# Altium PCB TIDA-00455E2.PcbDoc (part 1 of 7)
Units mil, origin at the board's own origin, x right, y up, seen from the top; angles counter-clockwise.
Board outline 6693 x 6693.1 mil, 8 copper layers (Layer 1 - Top Layer, Layer 2 - GND, Layer 3 - Sensitive, Layer 4 - GND, Layer 5 - PWR, Layer 6 - Signal, Layer 7 - GND, Layer 8 - Bottom Layer), stack 63.122 mil thick; 537 components, 407 nets, 1686 pads, 1249 vias.
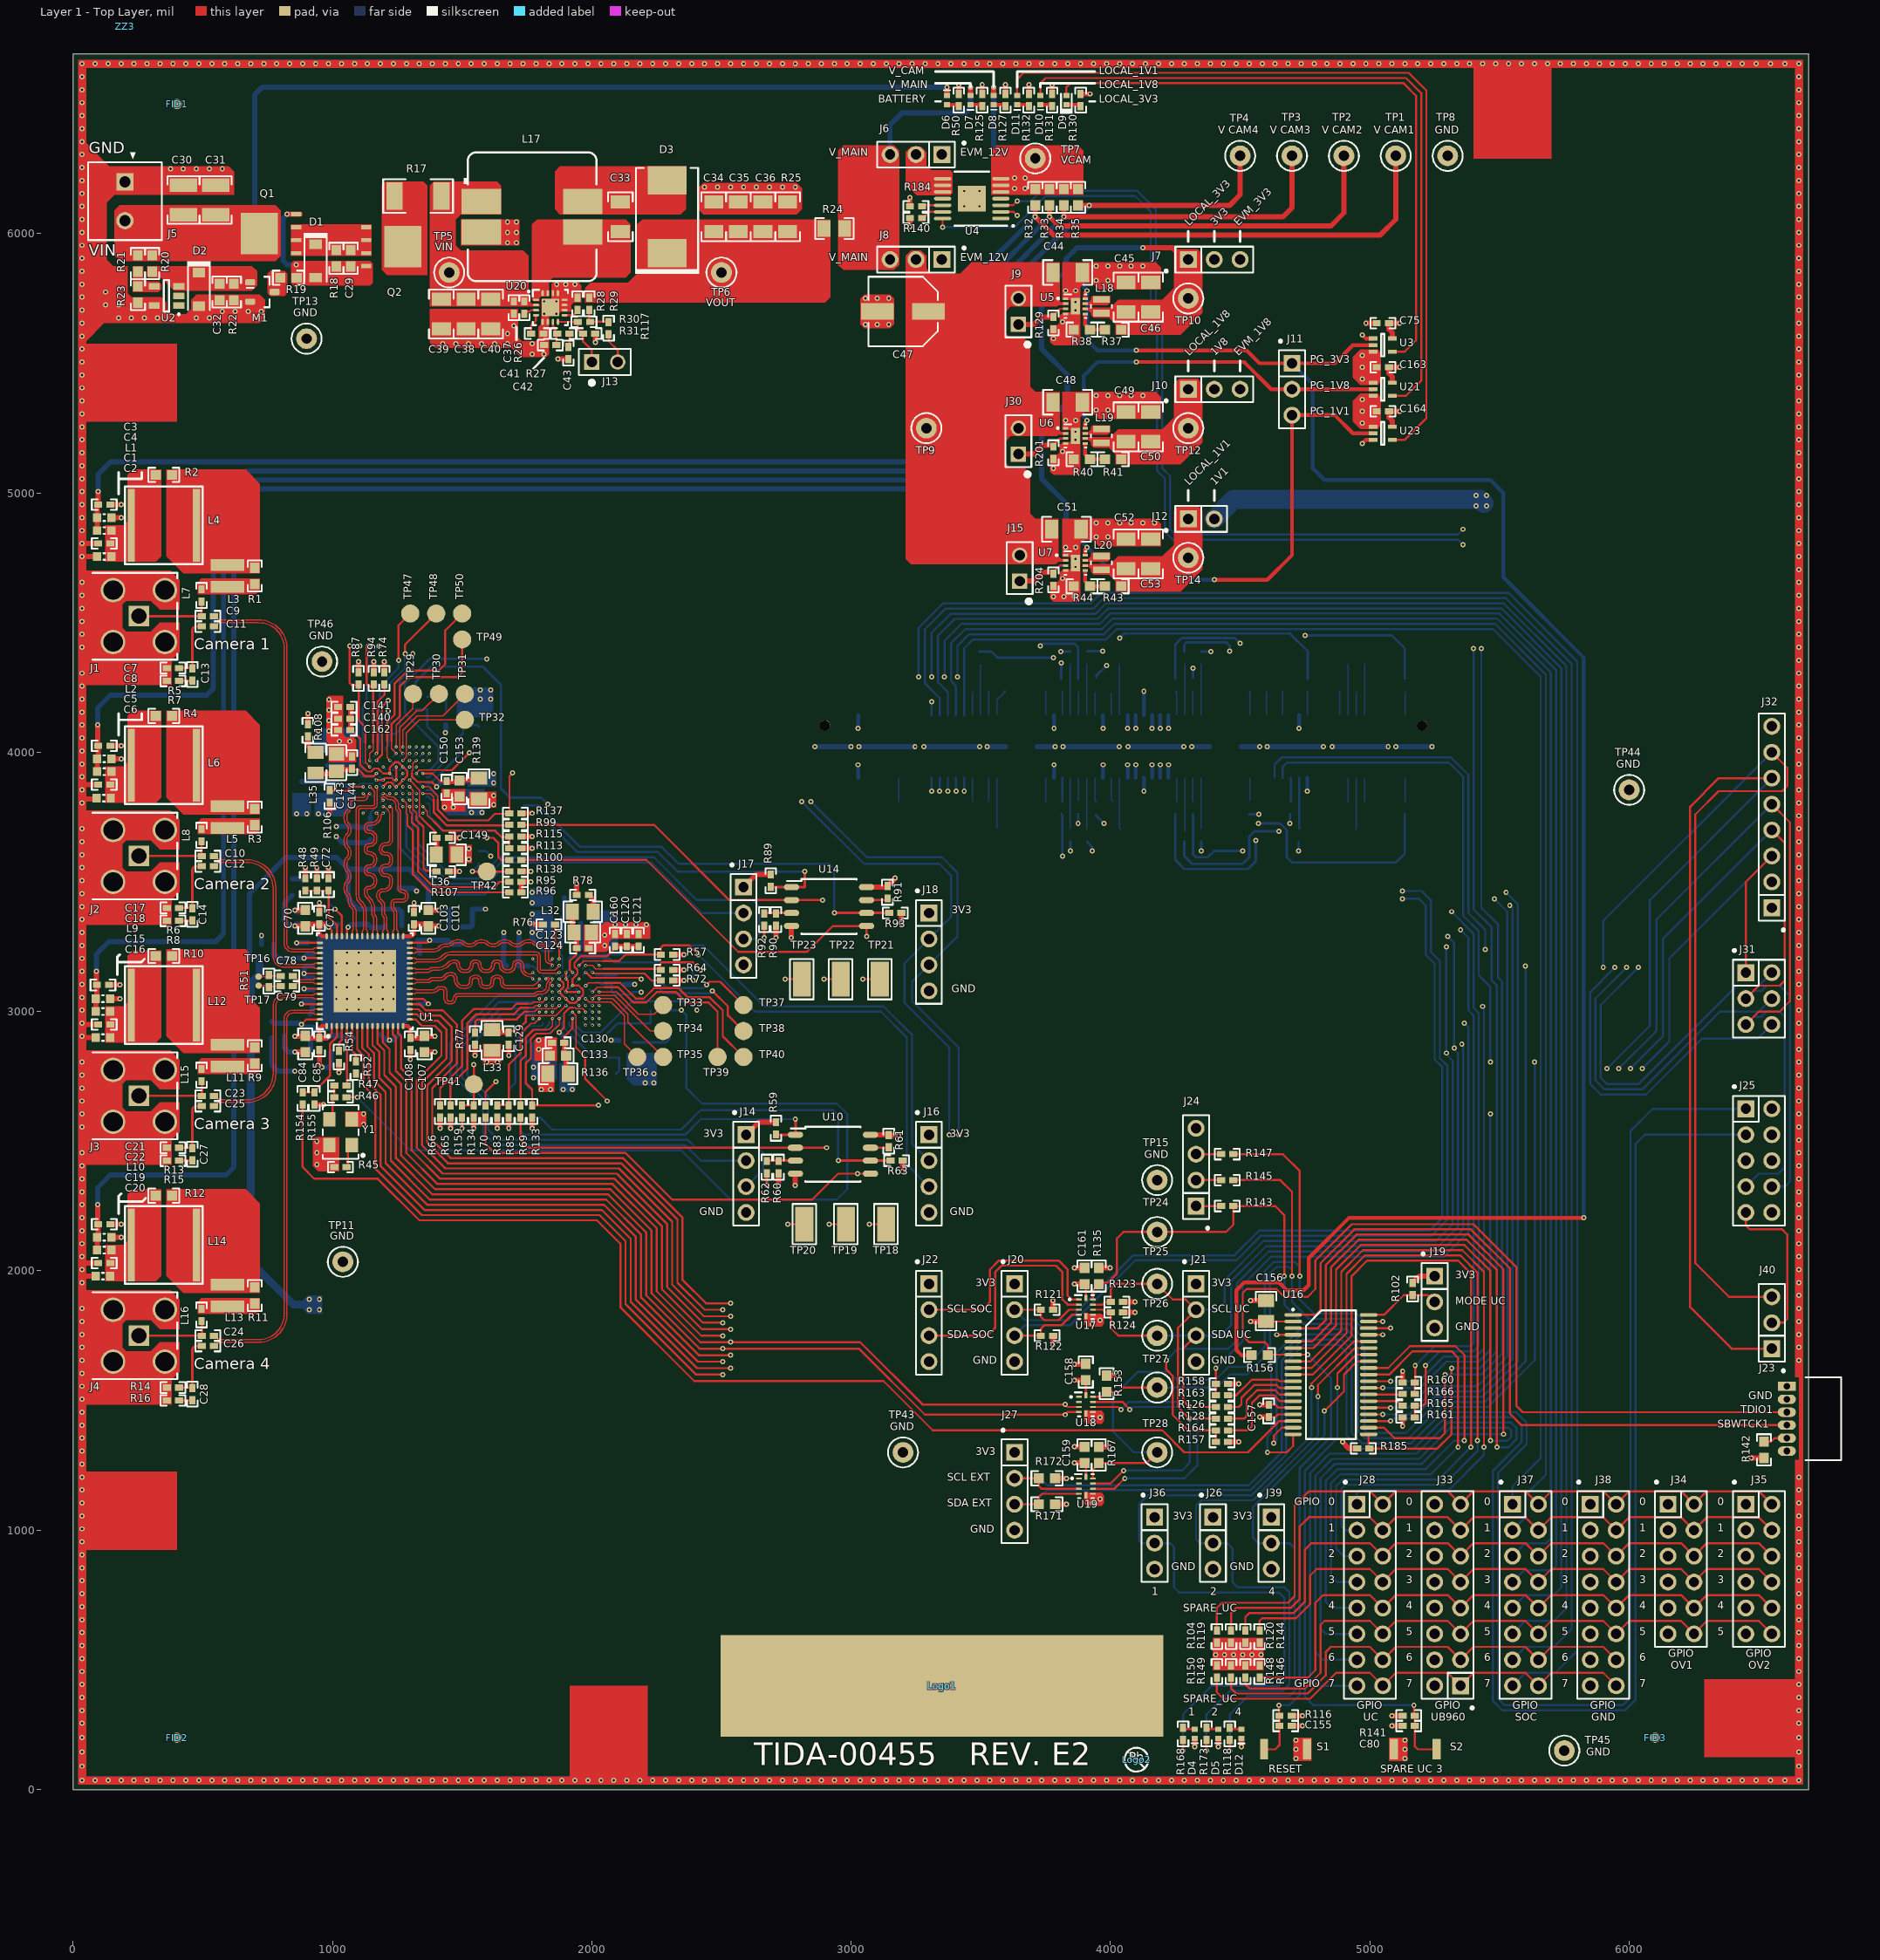
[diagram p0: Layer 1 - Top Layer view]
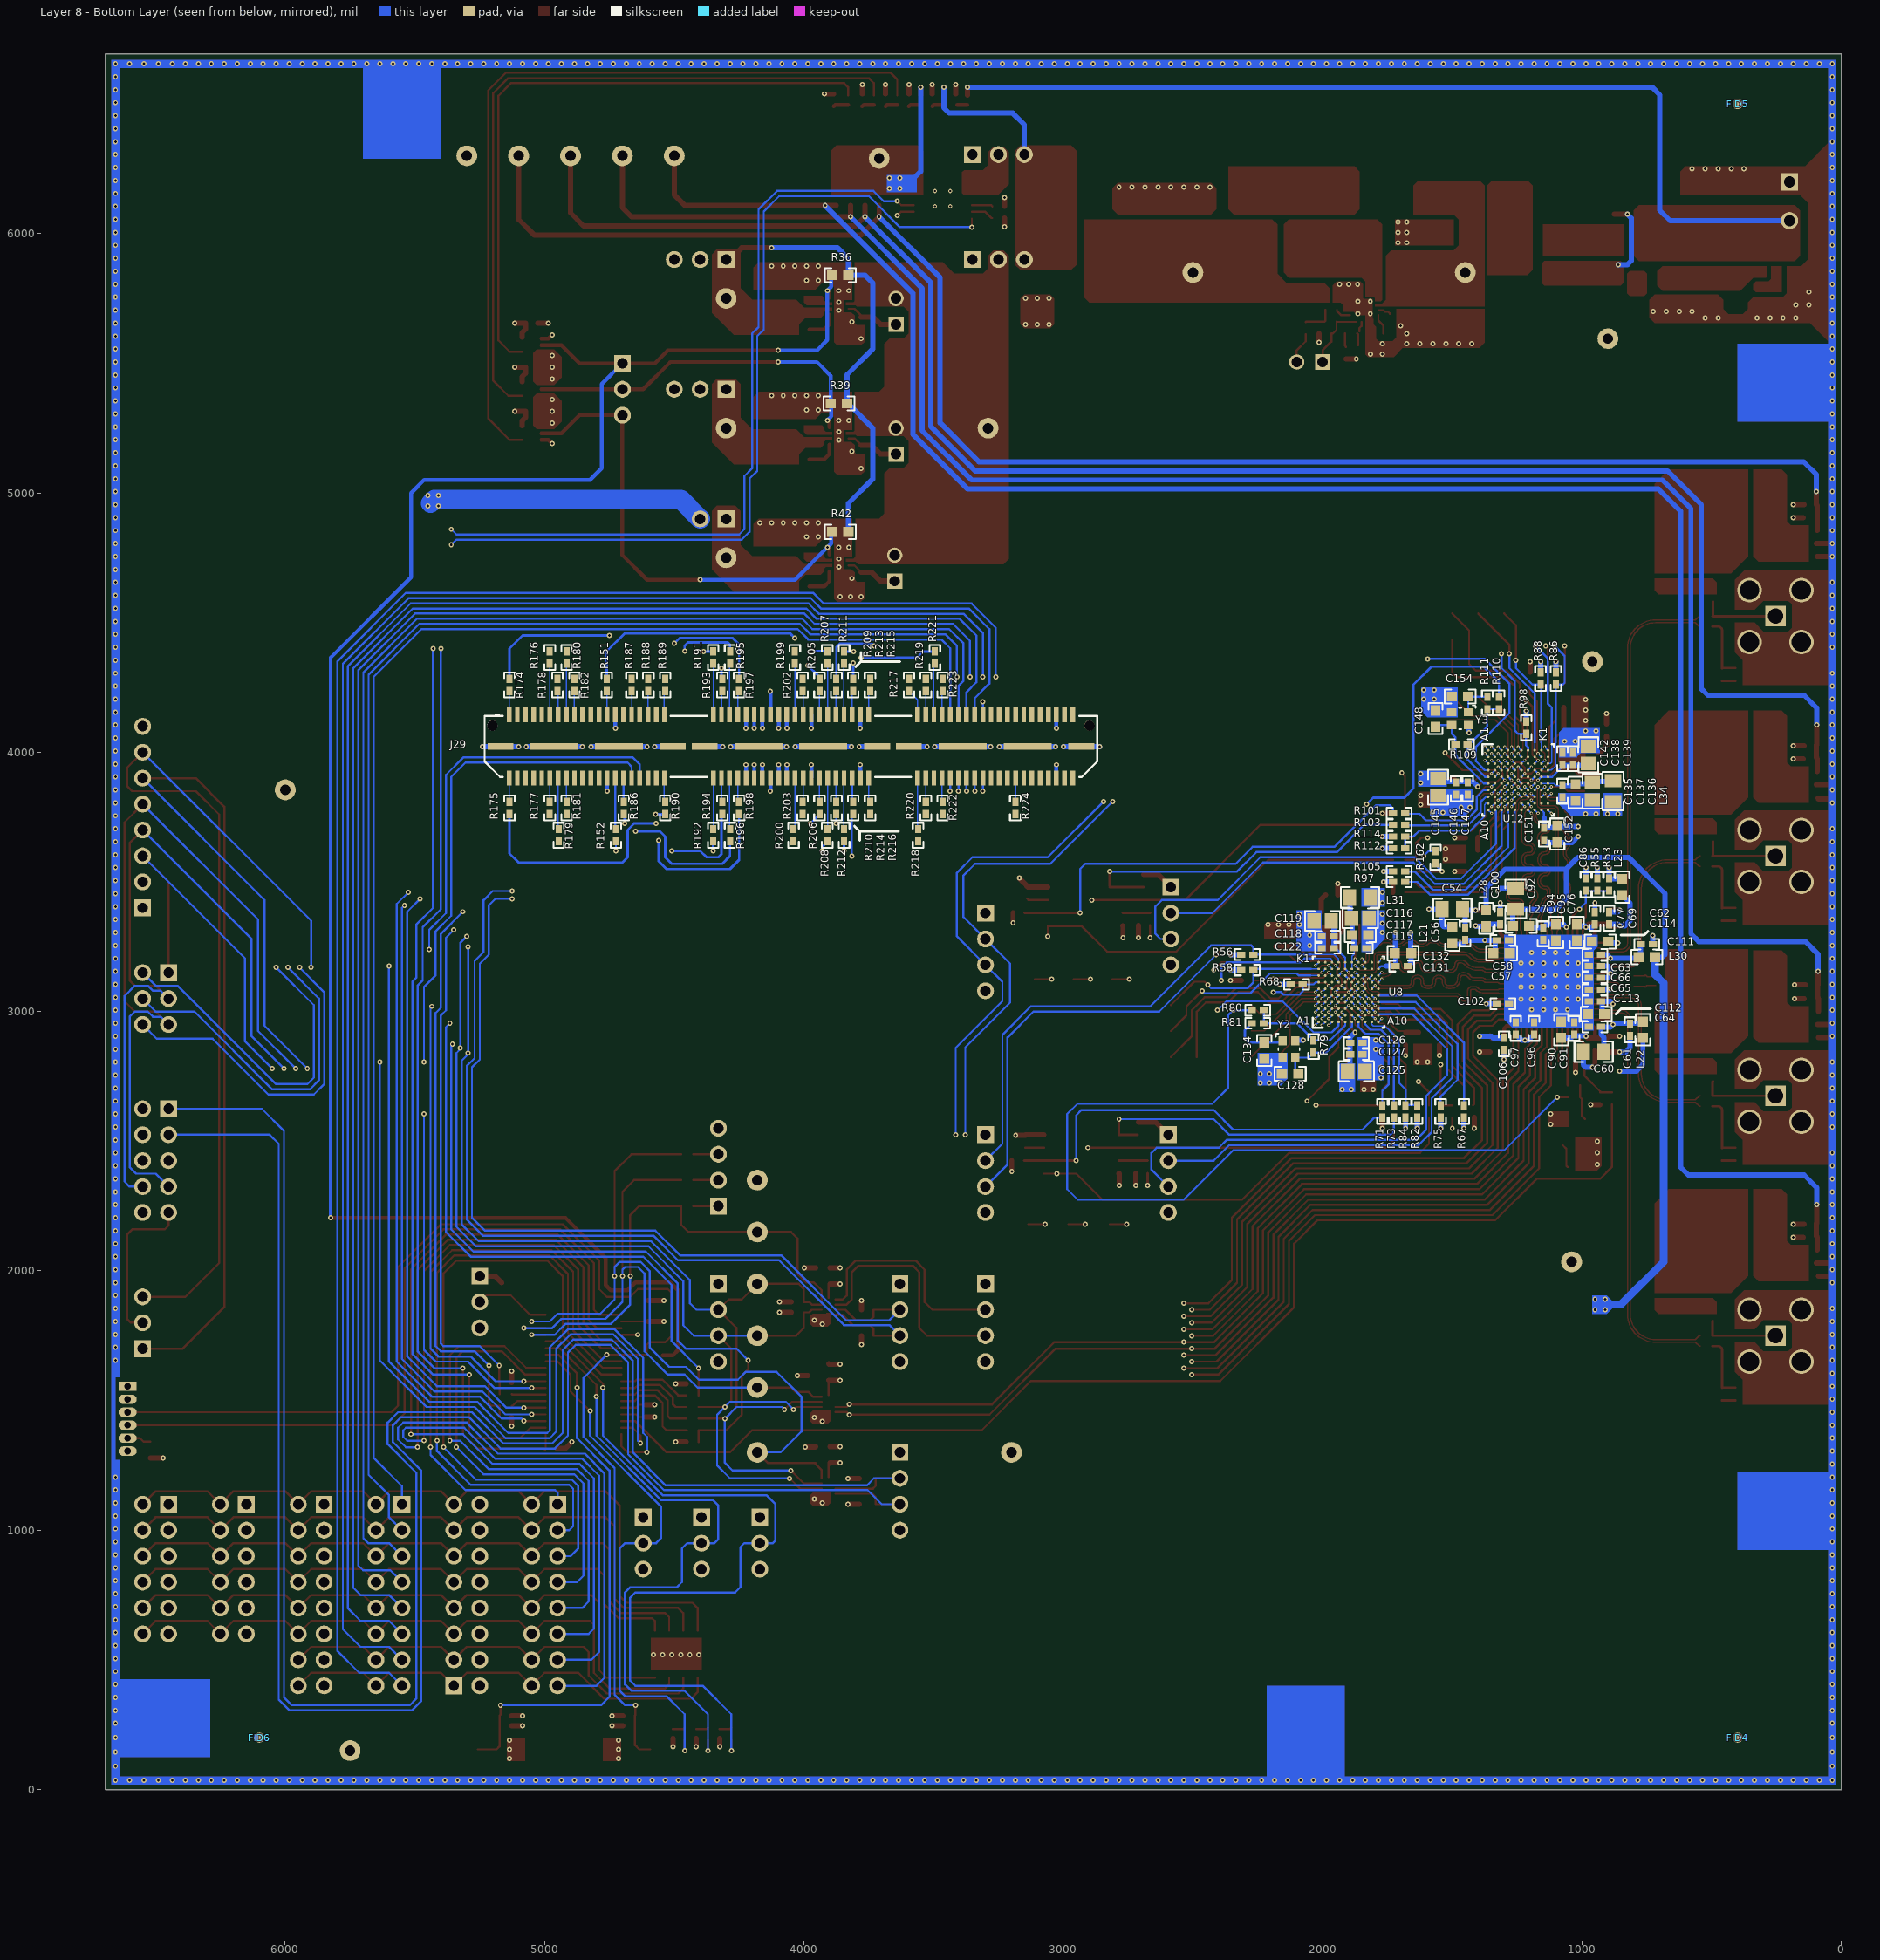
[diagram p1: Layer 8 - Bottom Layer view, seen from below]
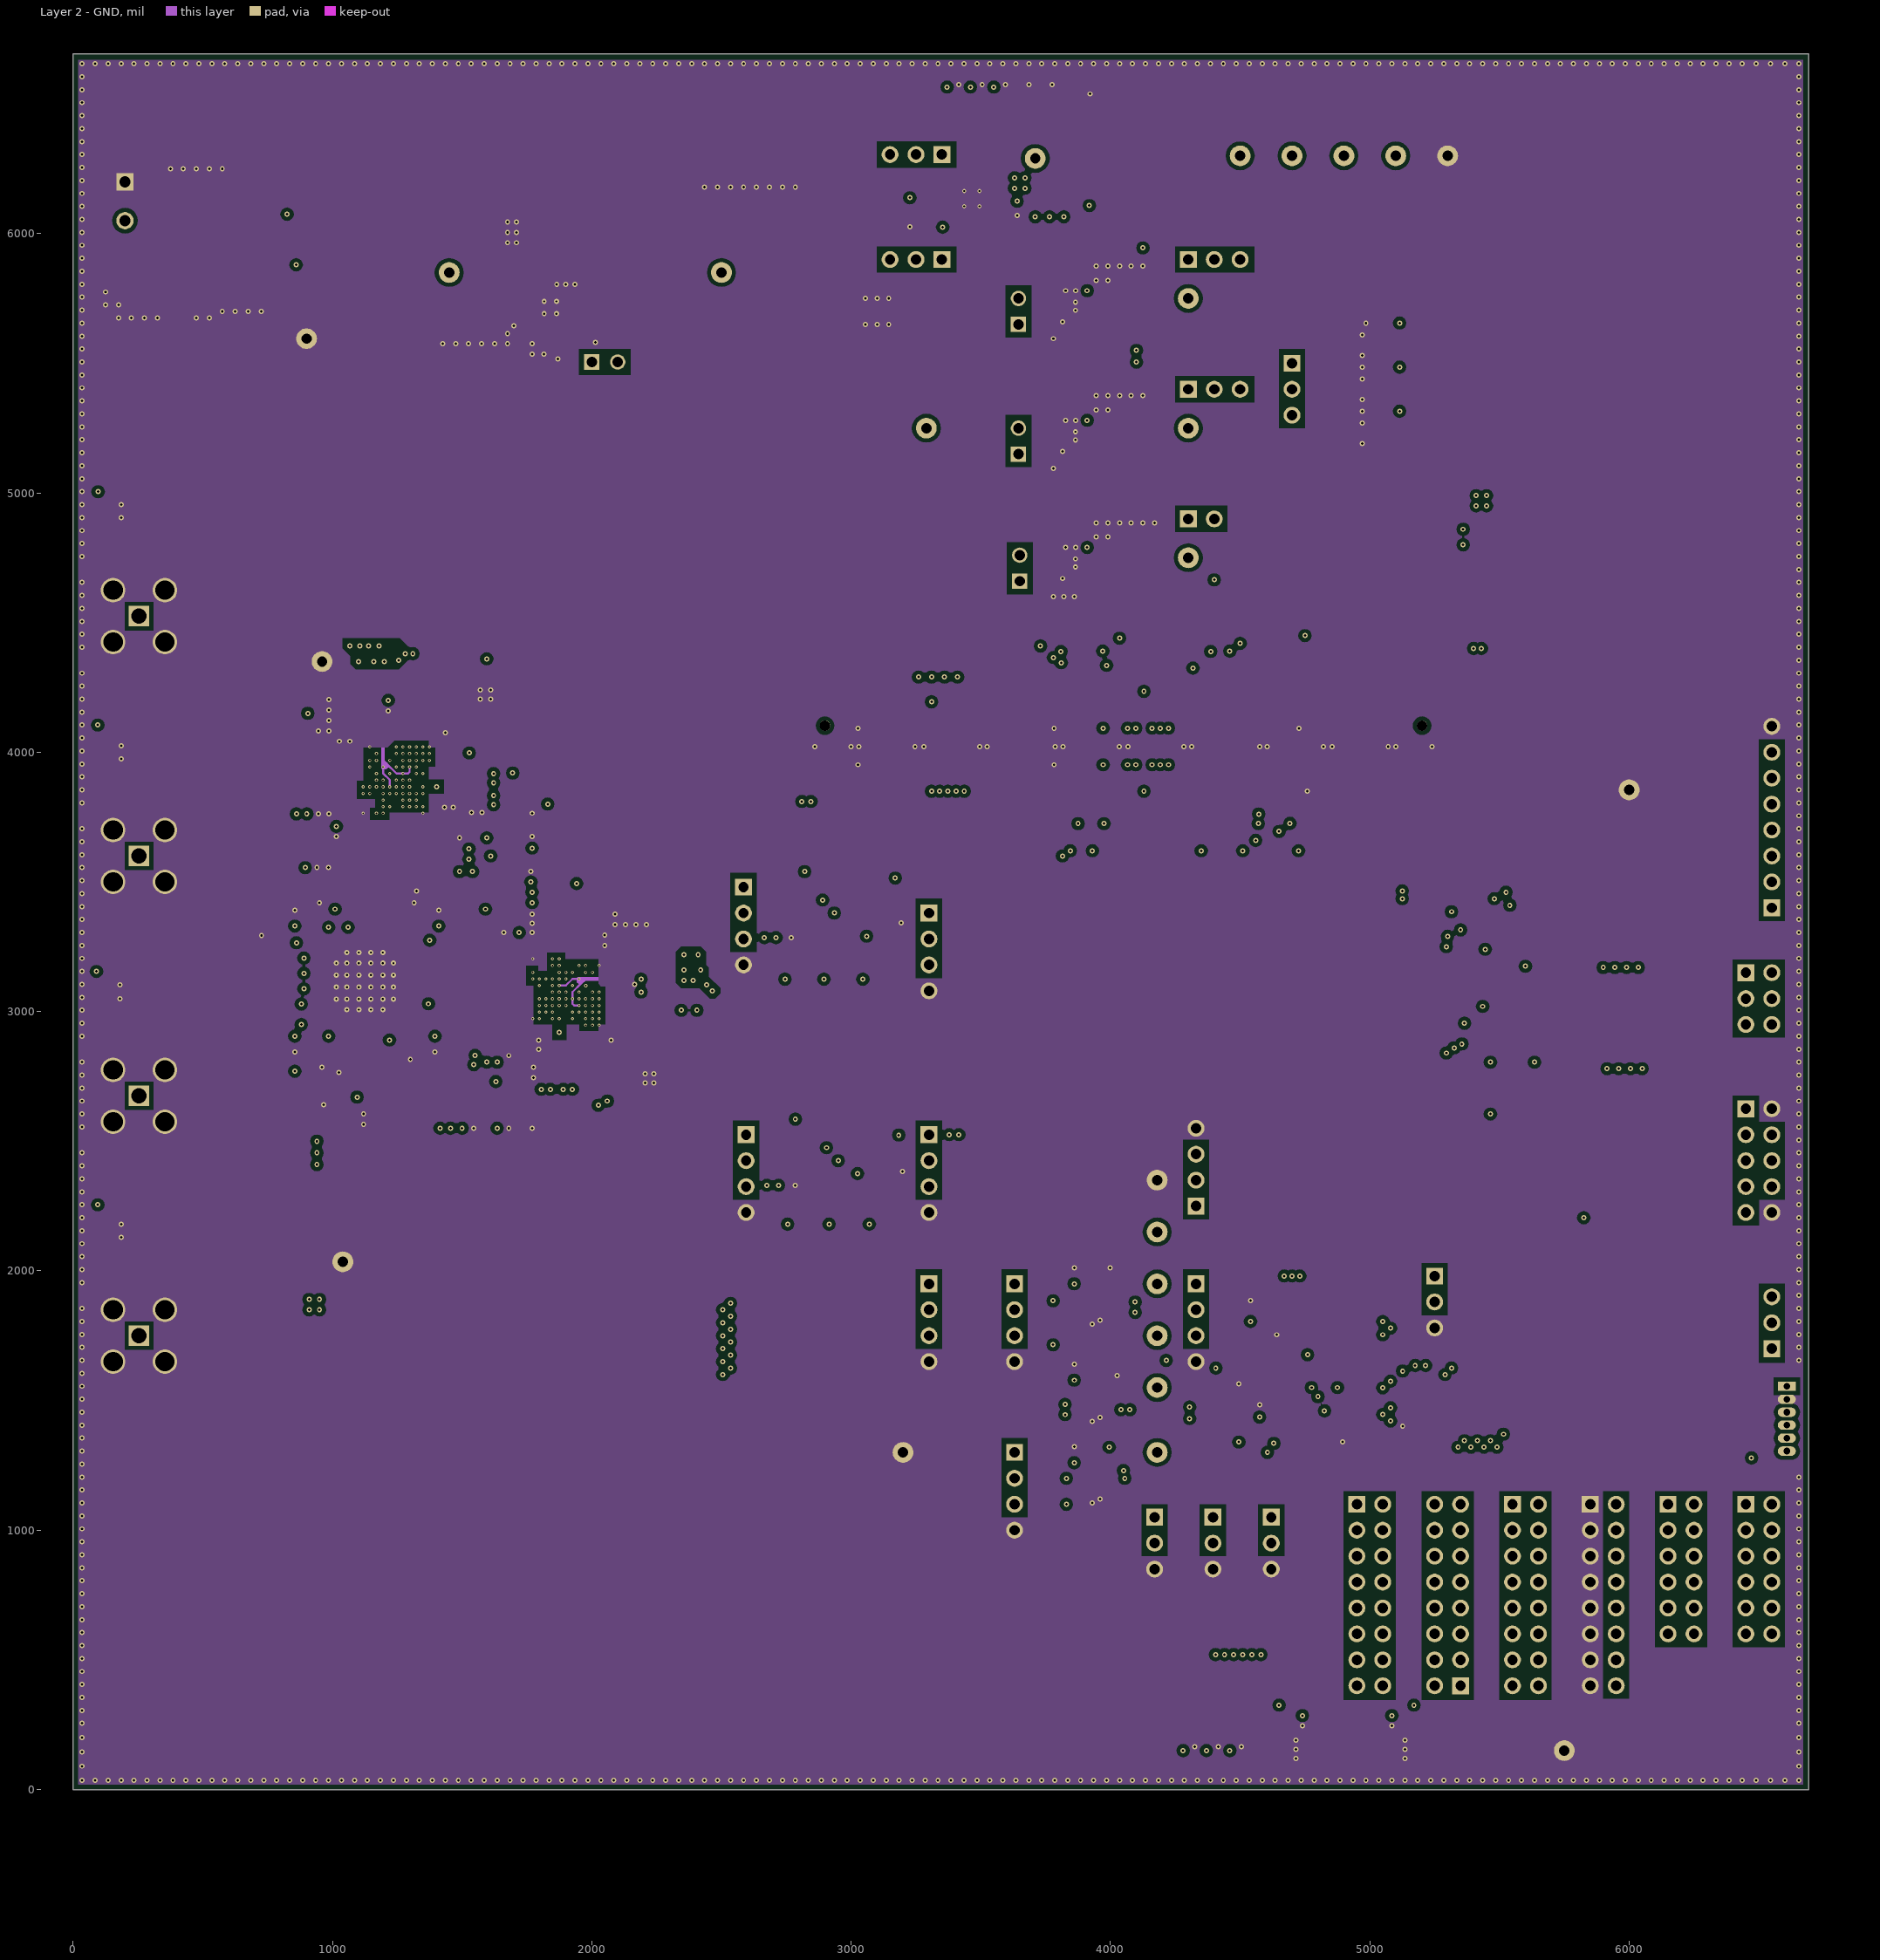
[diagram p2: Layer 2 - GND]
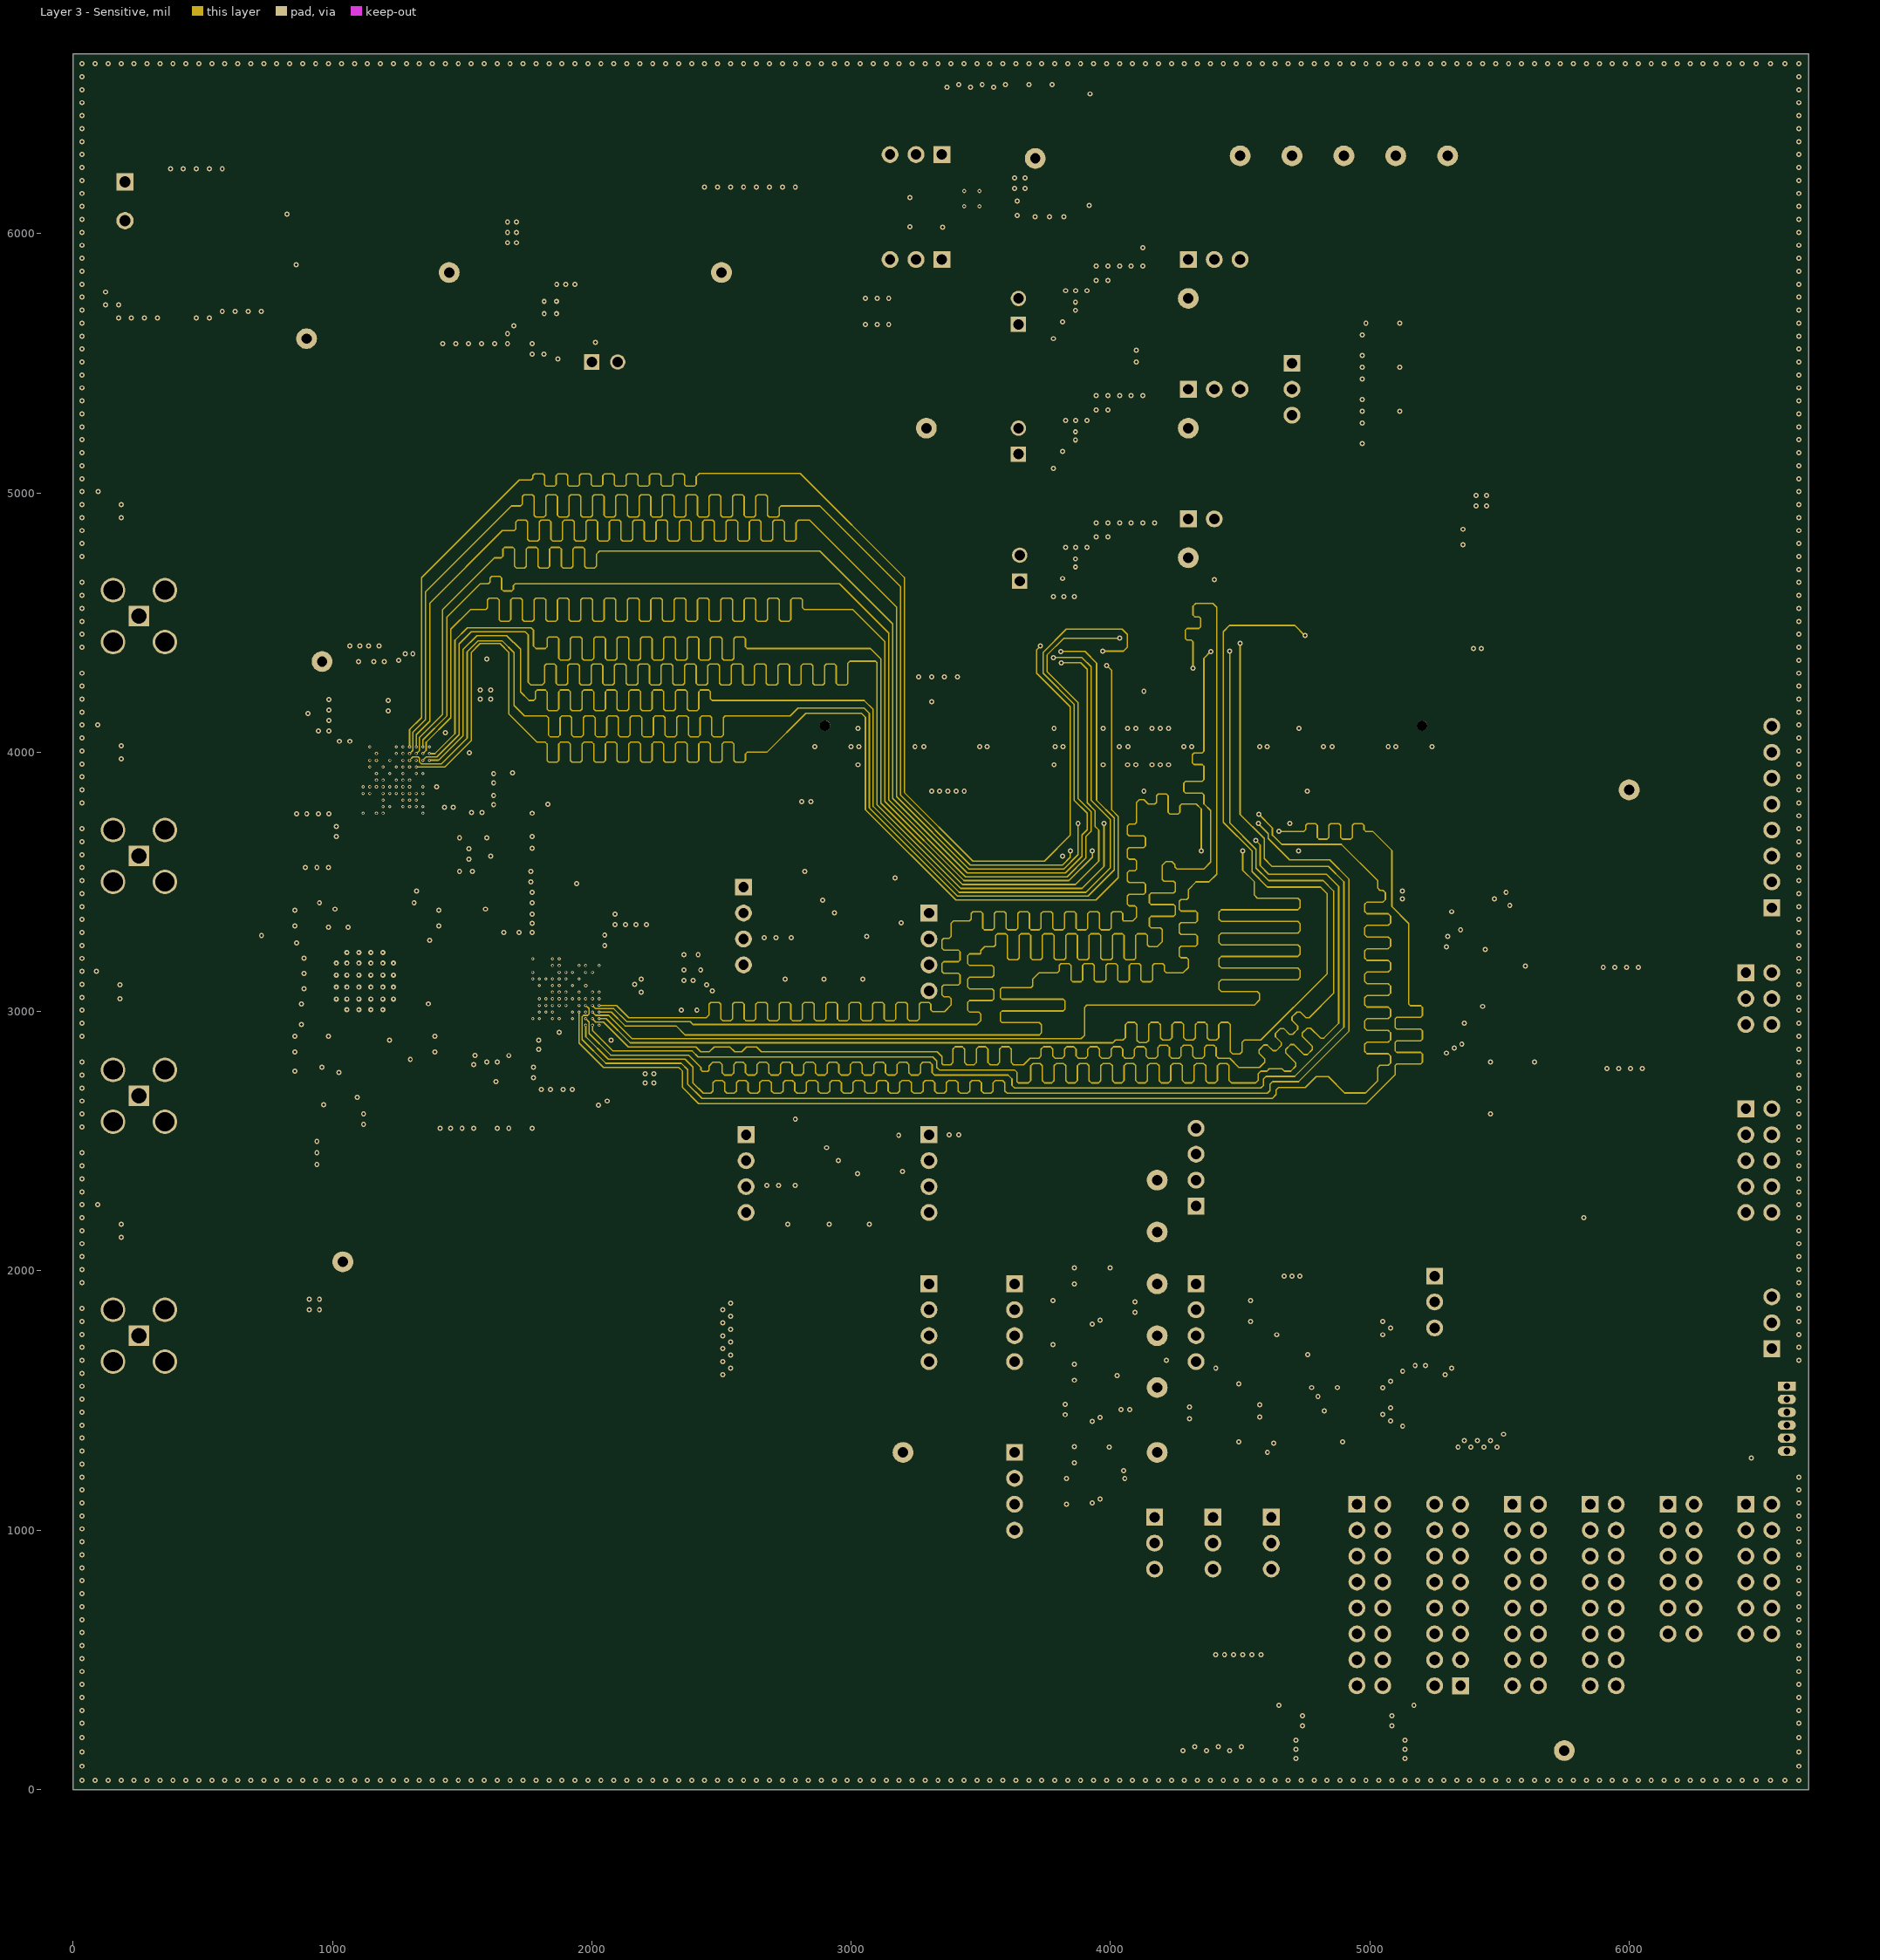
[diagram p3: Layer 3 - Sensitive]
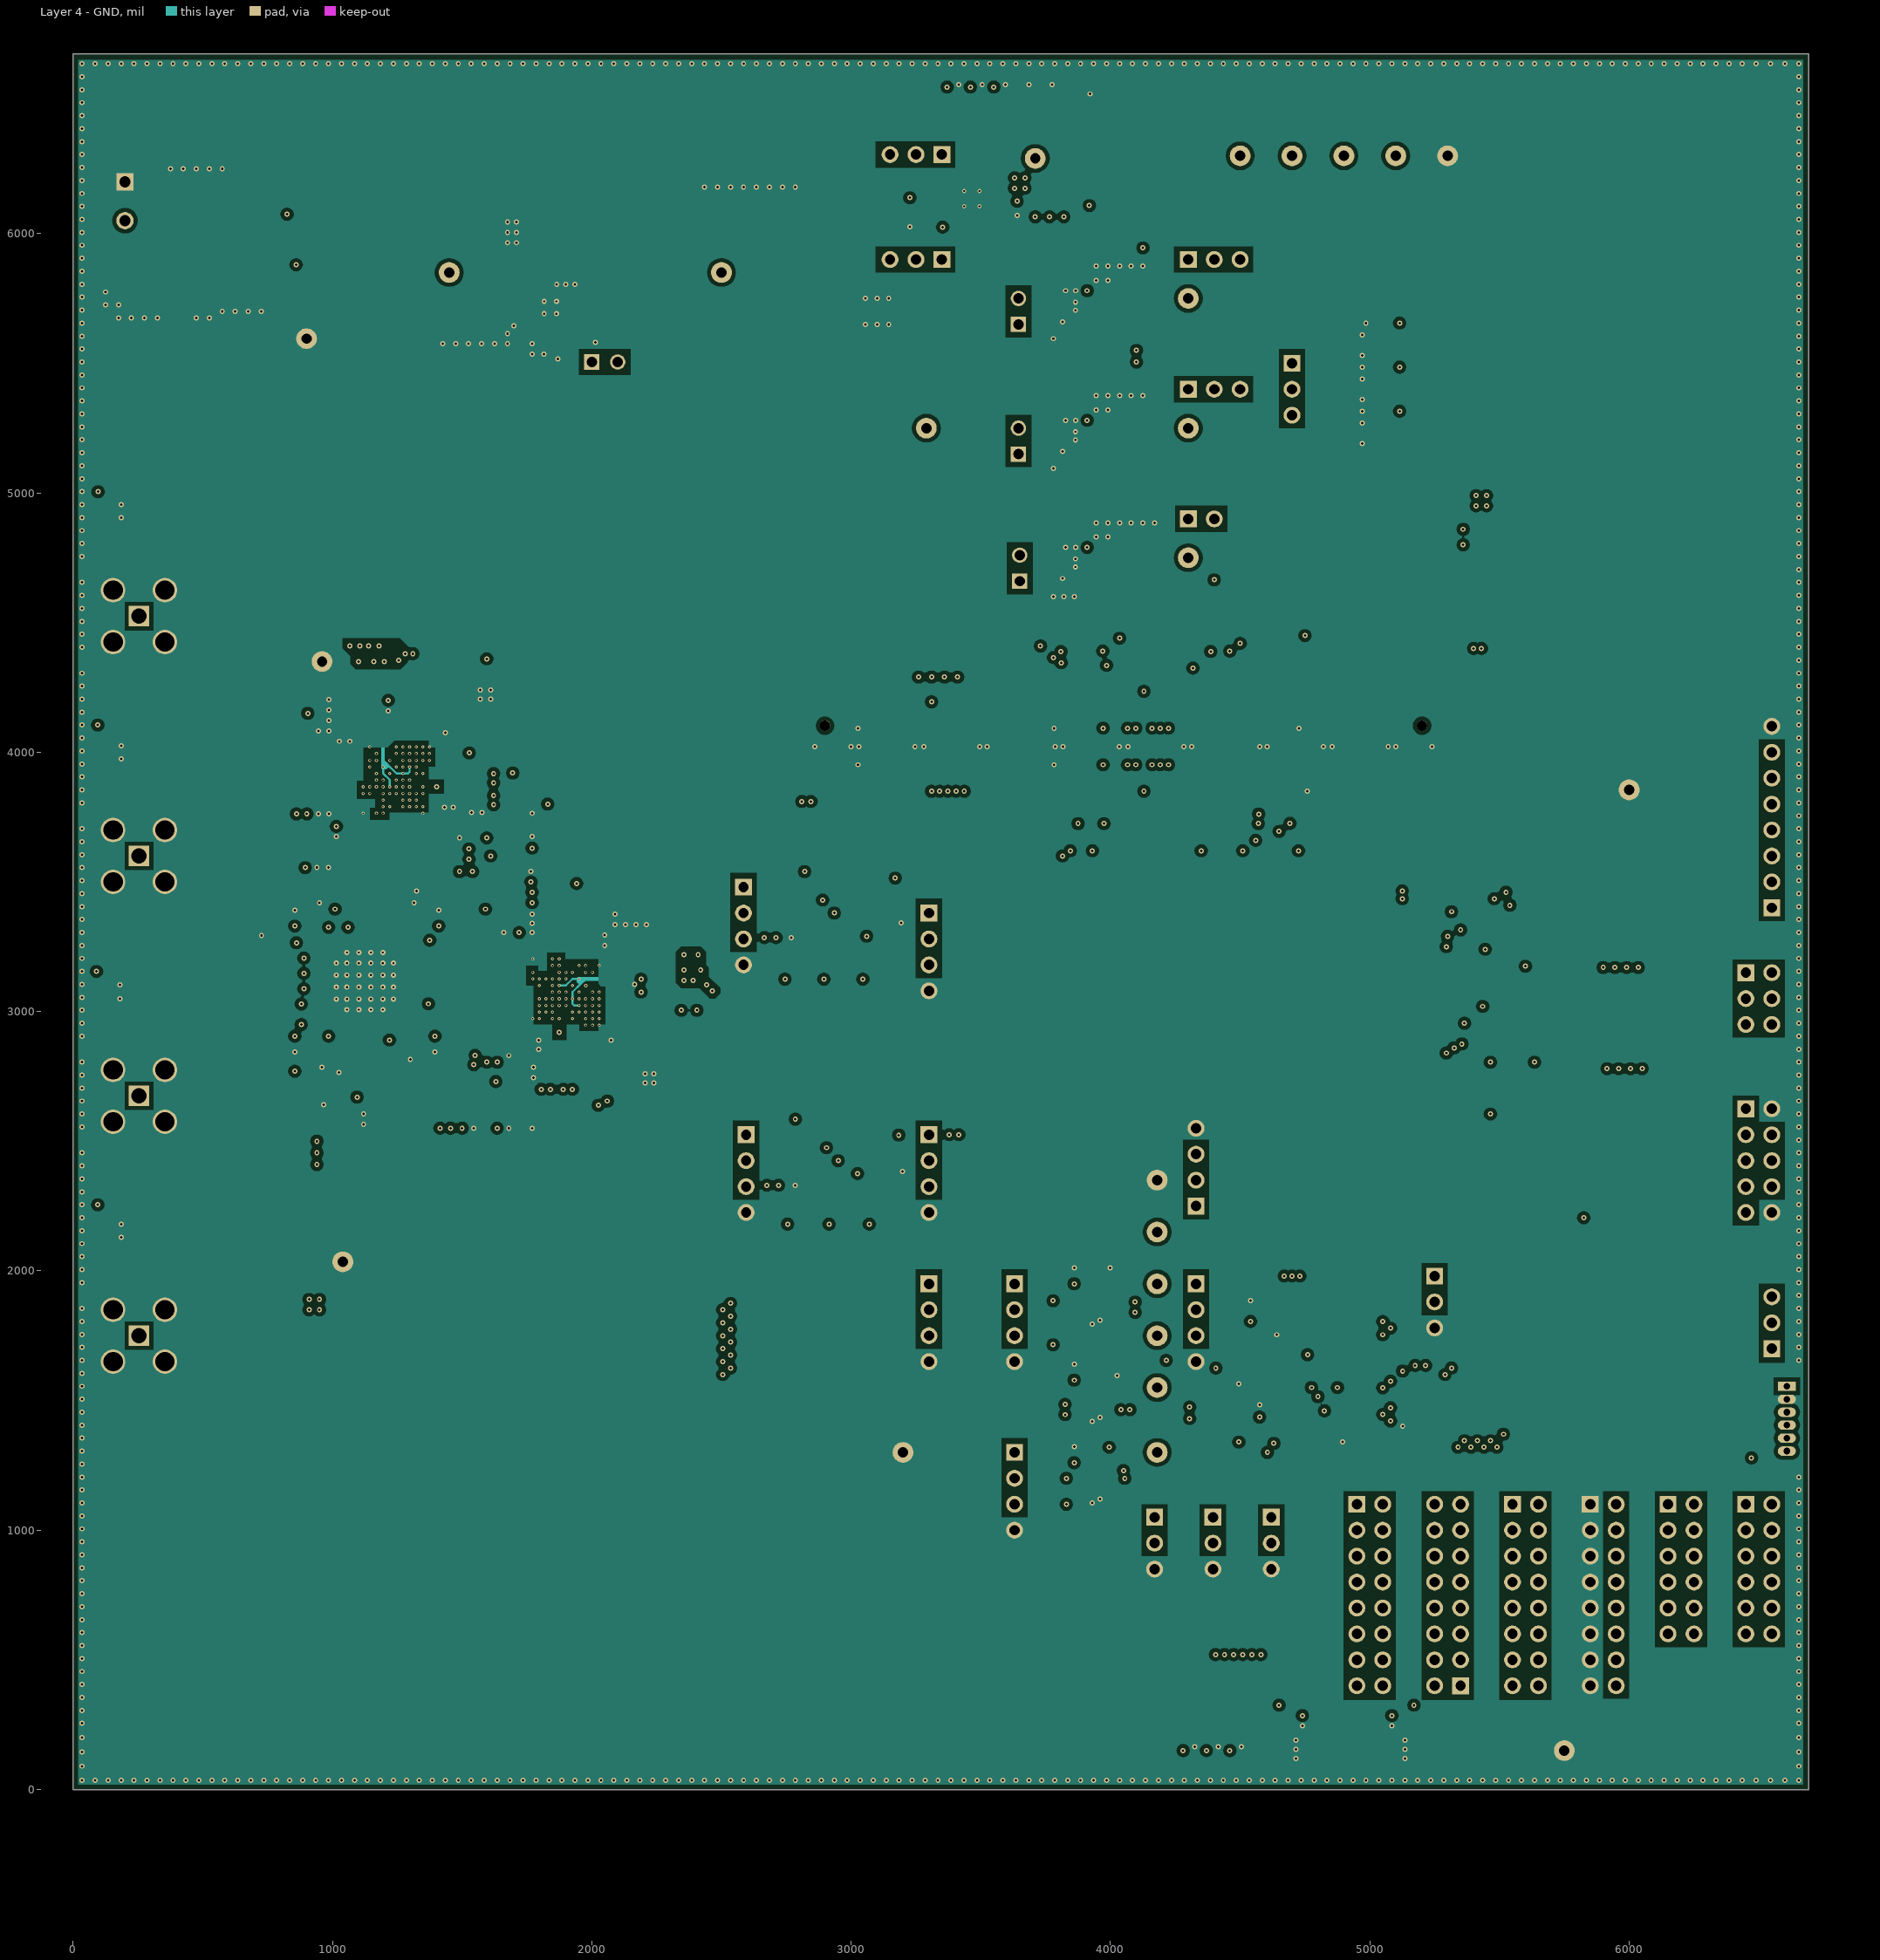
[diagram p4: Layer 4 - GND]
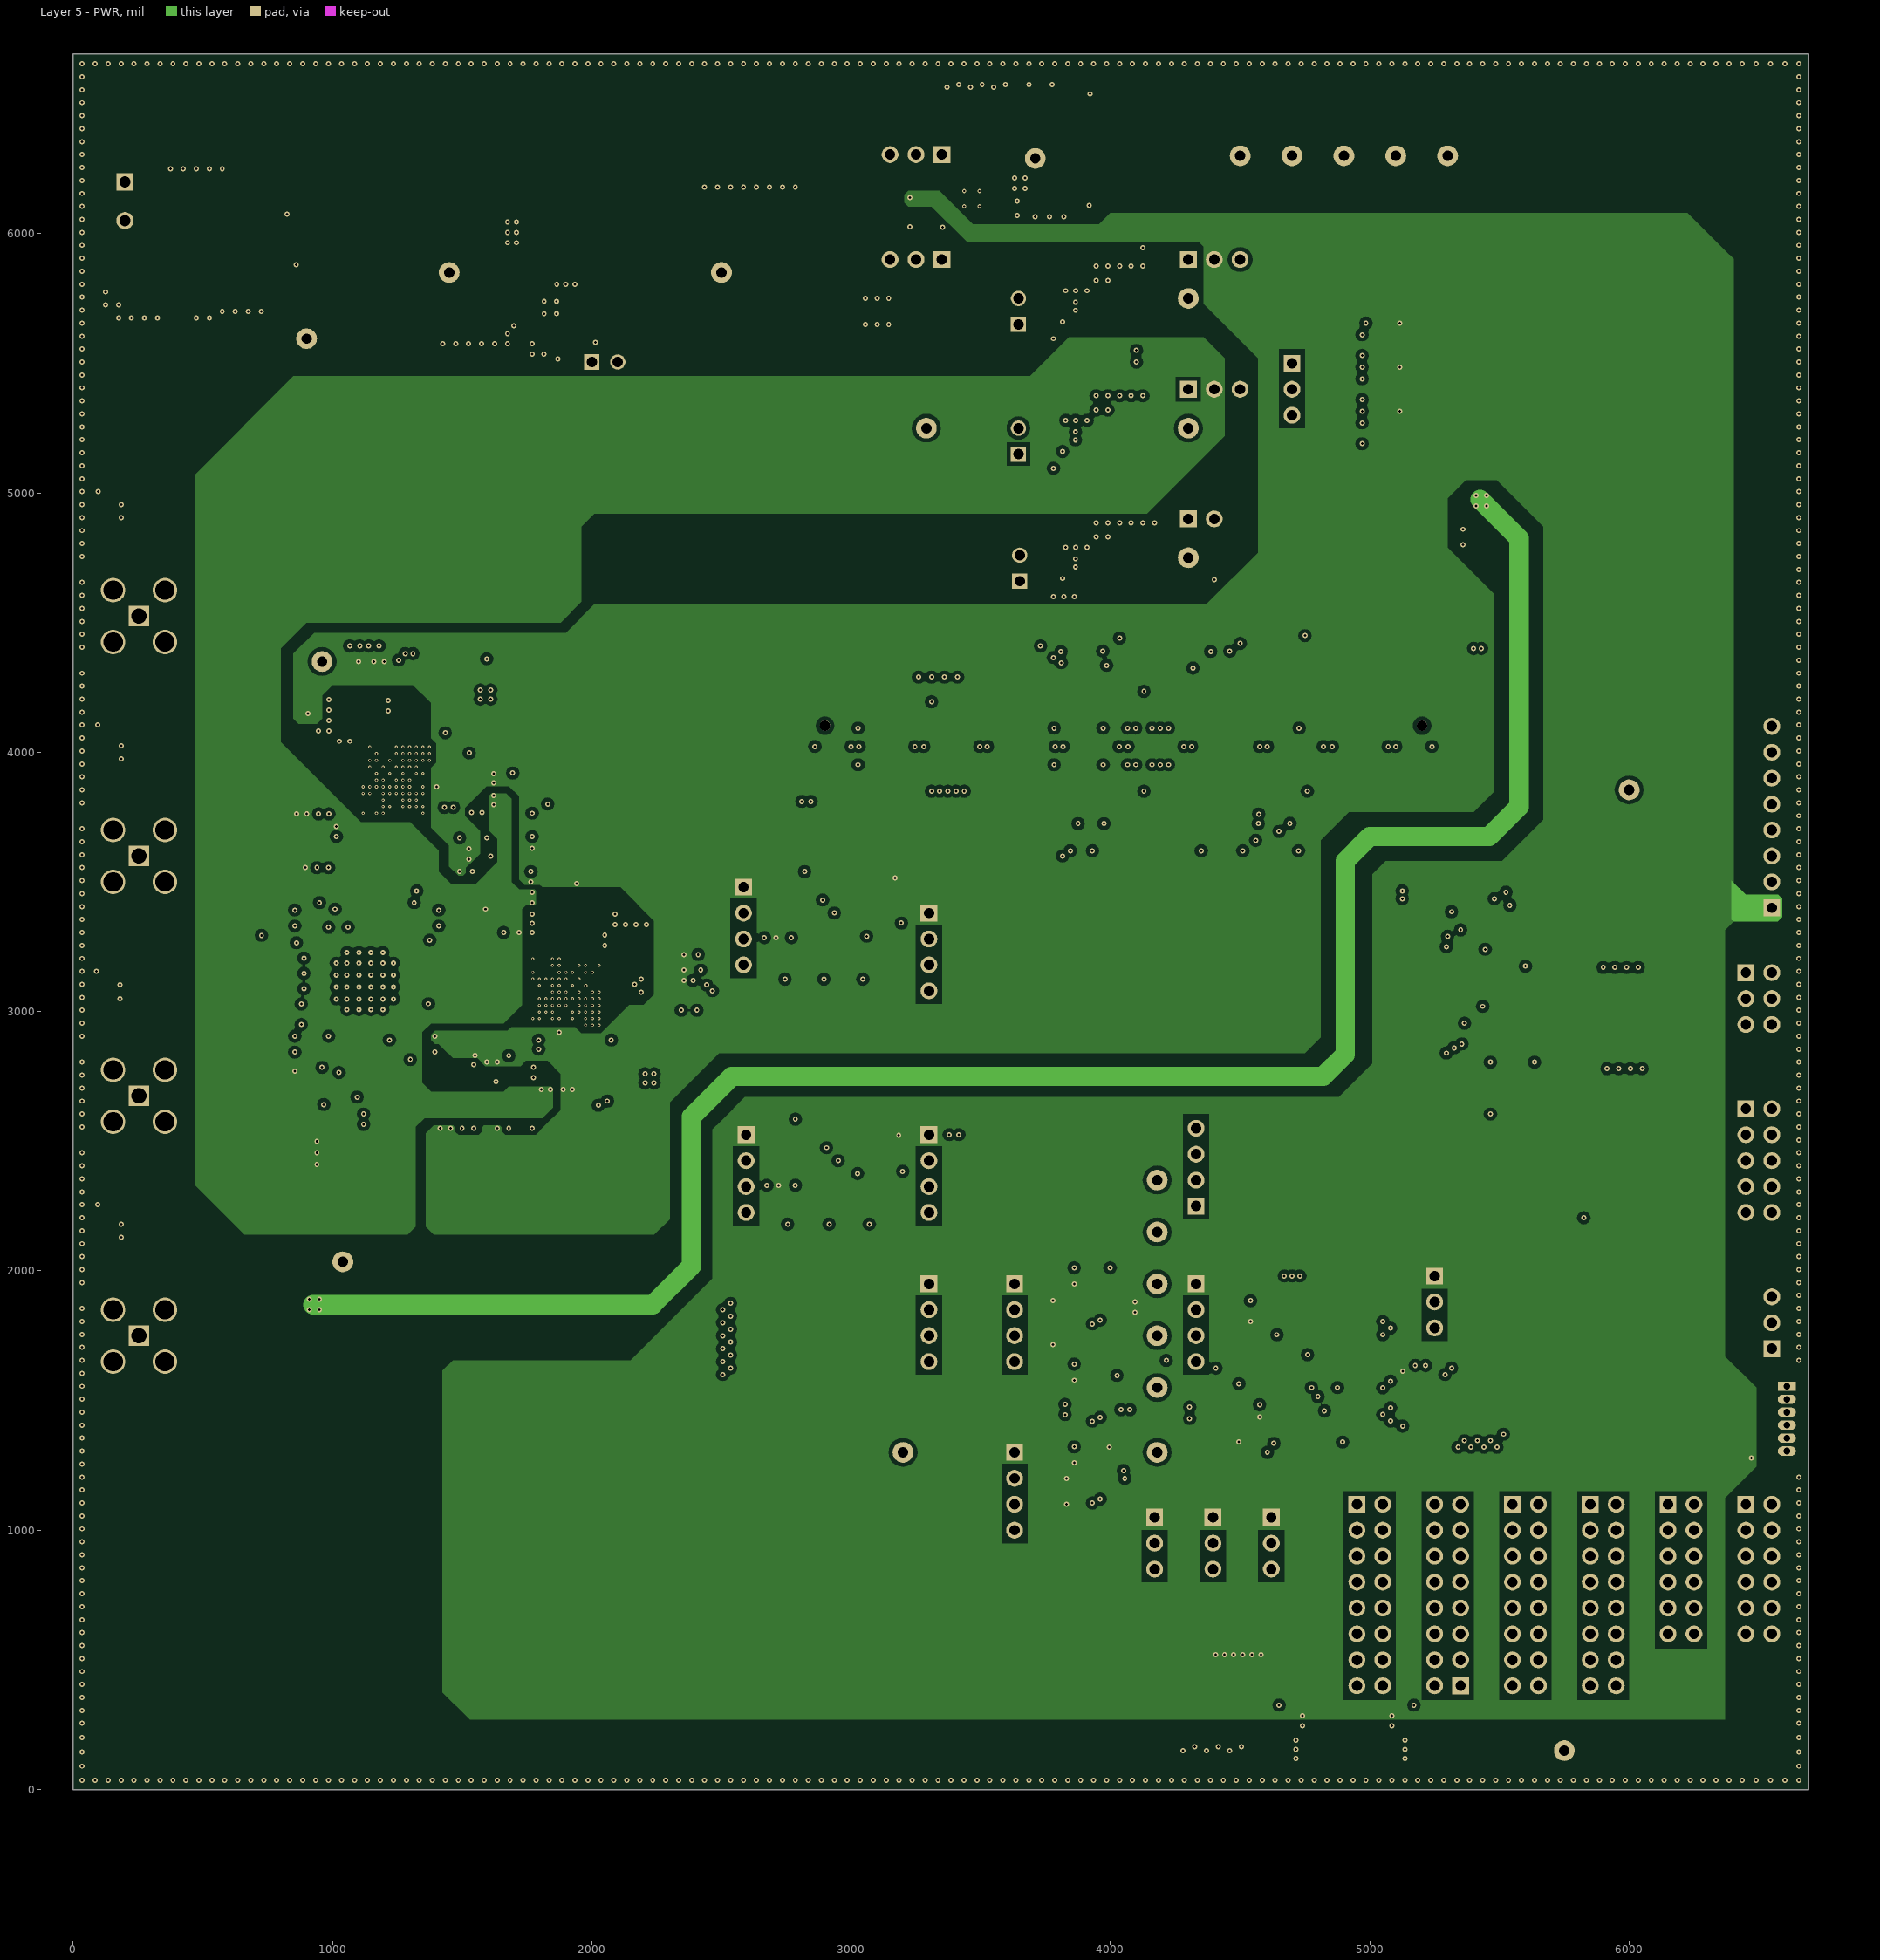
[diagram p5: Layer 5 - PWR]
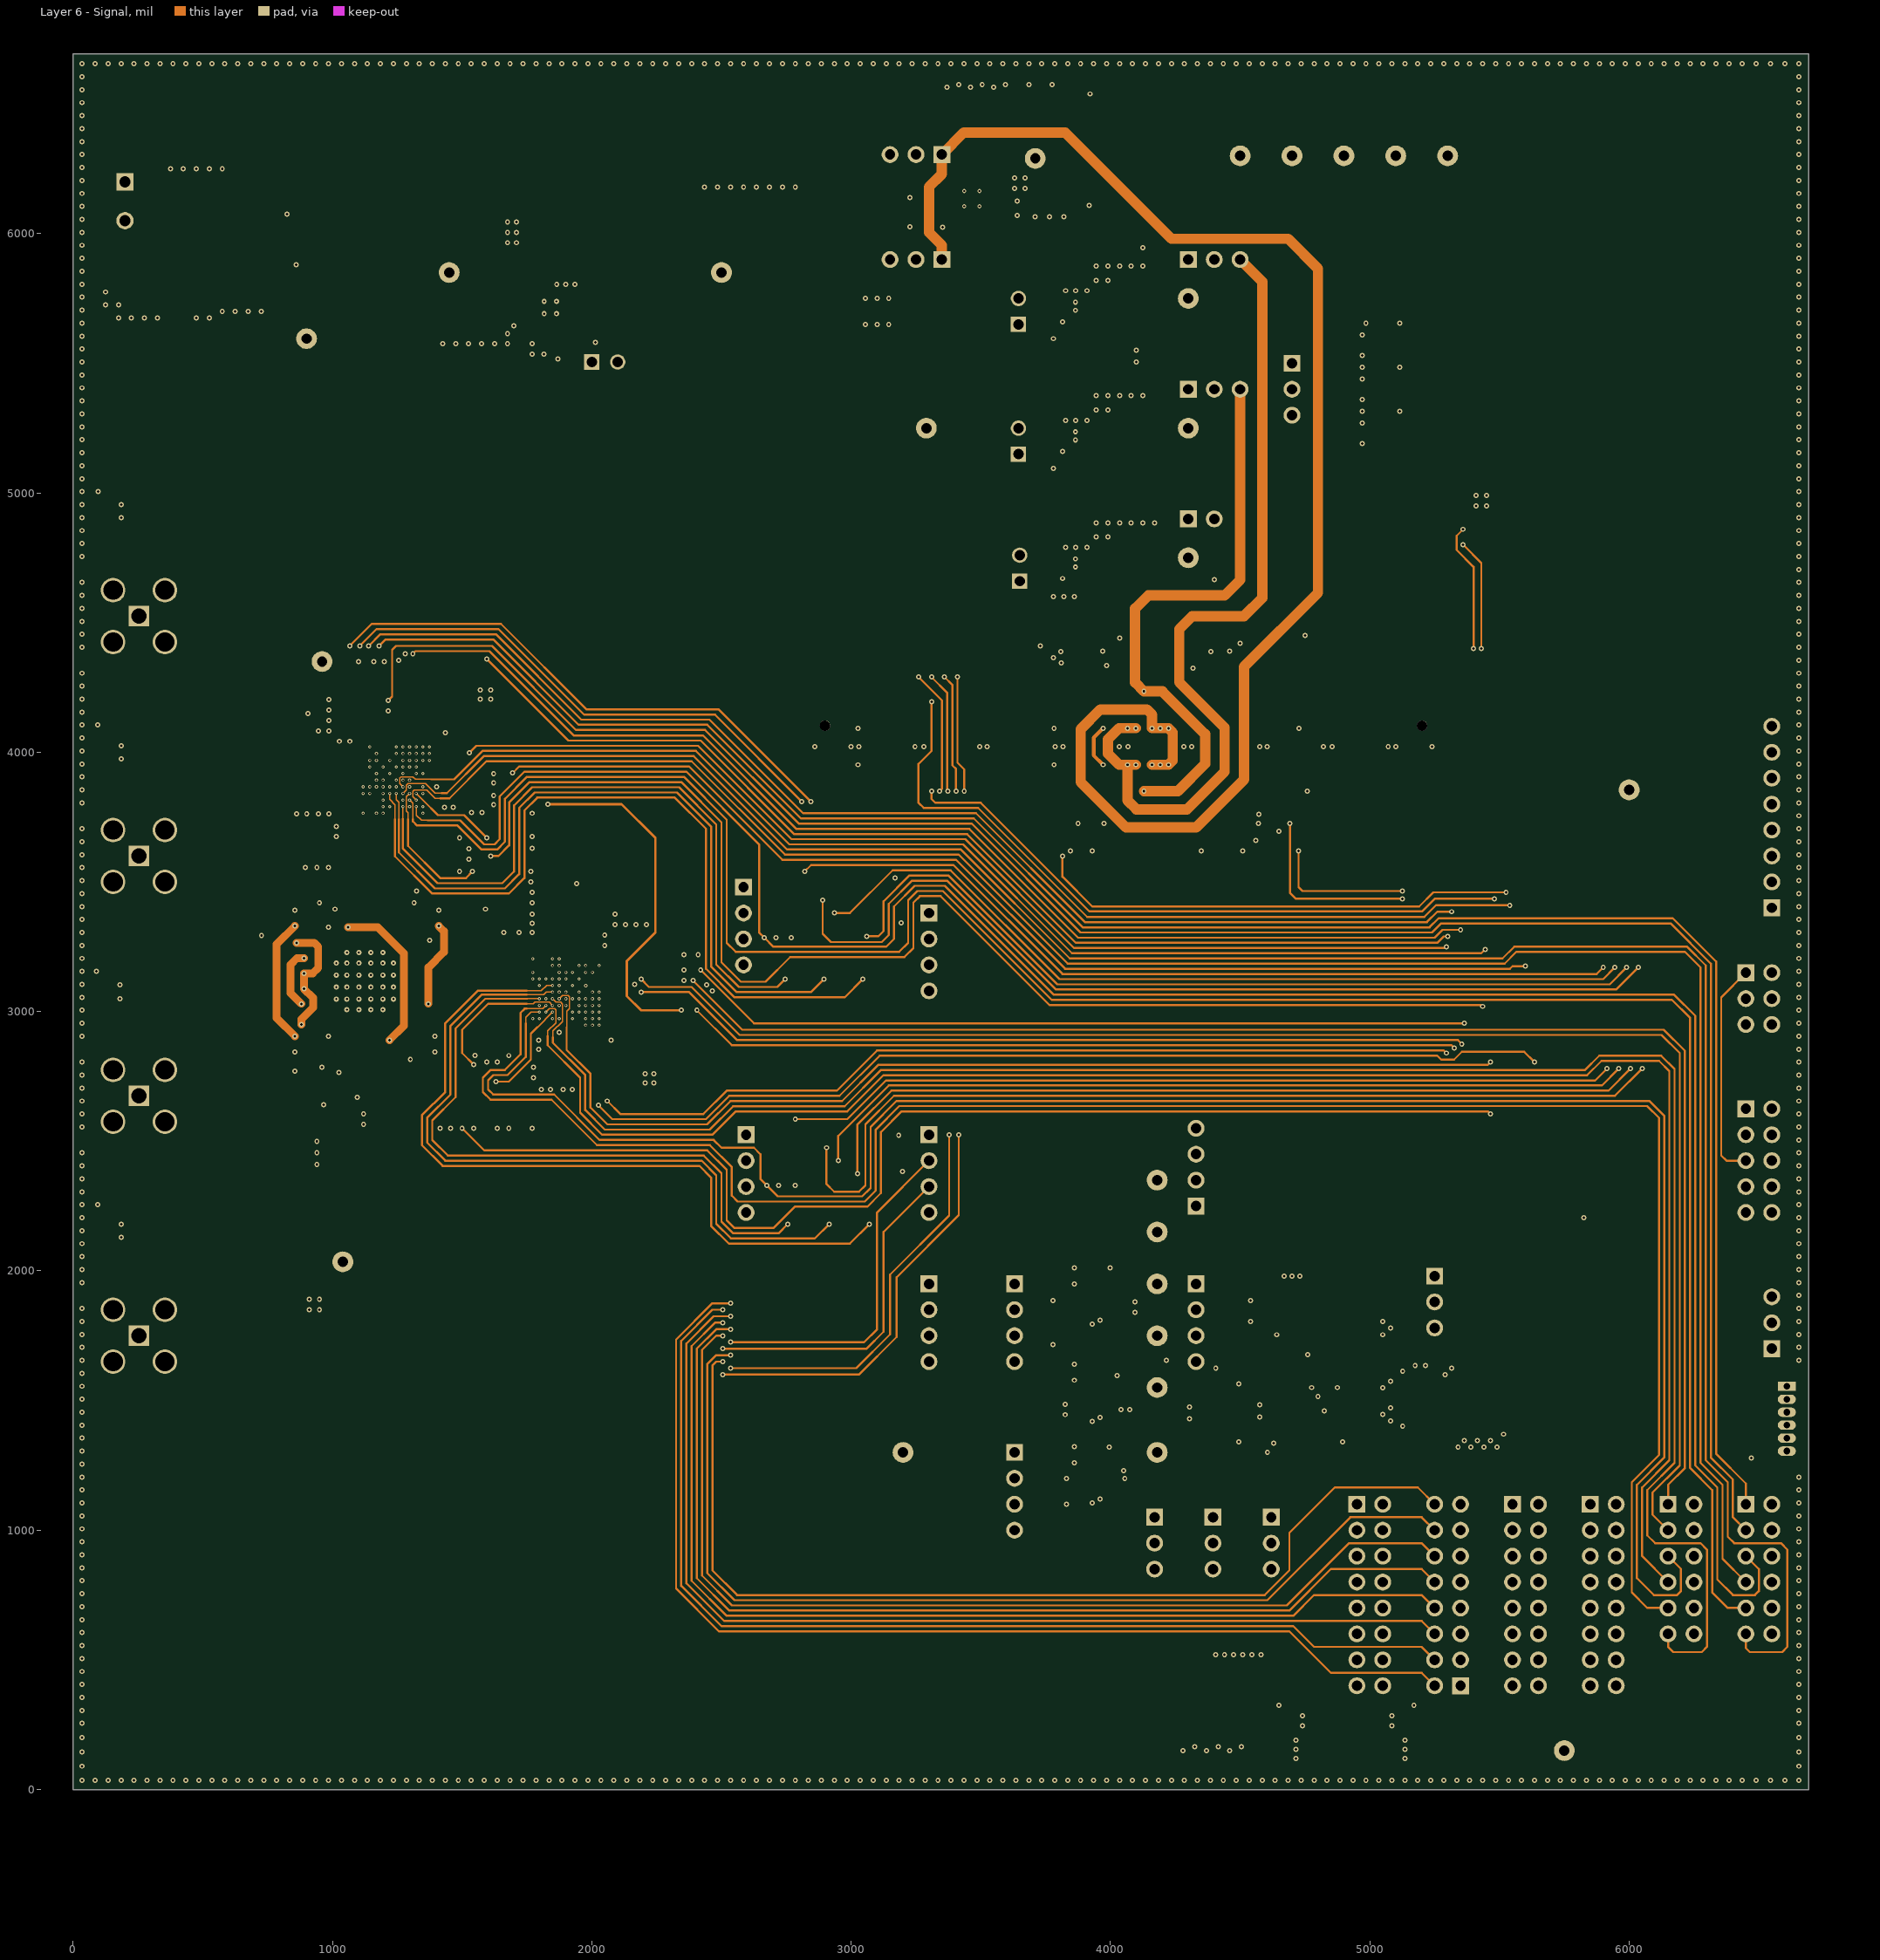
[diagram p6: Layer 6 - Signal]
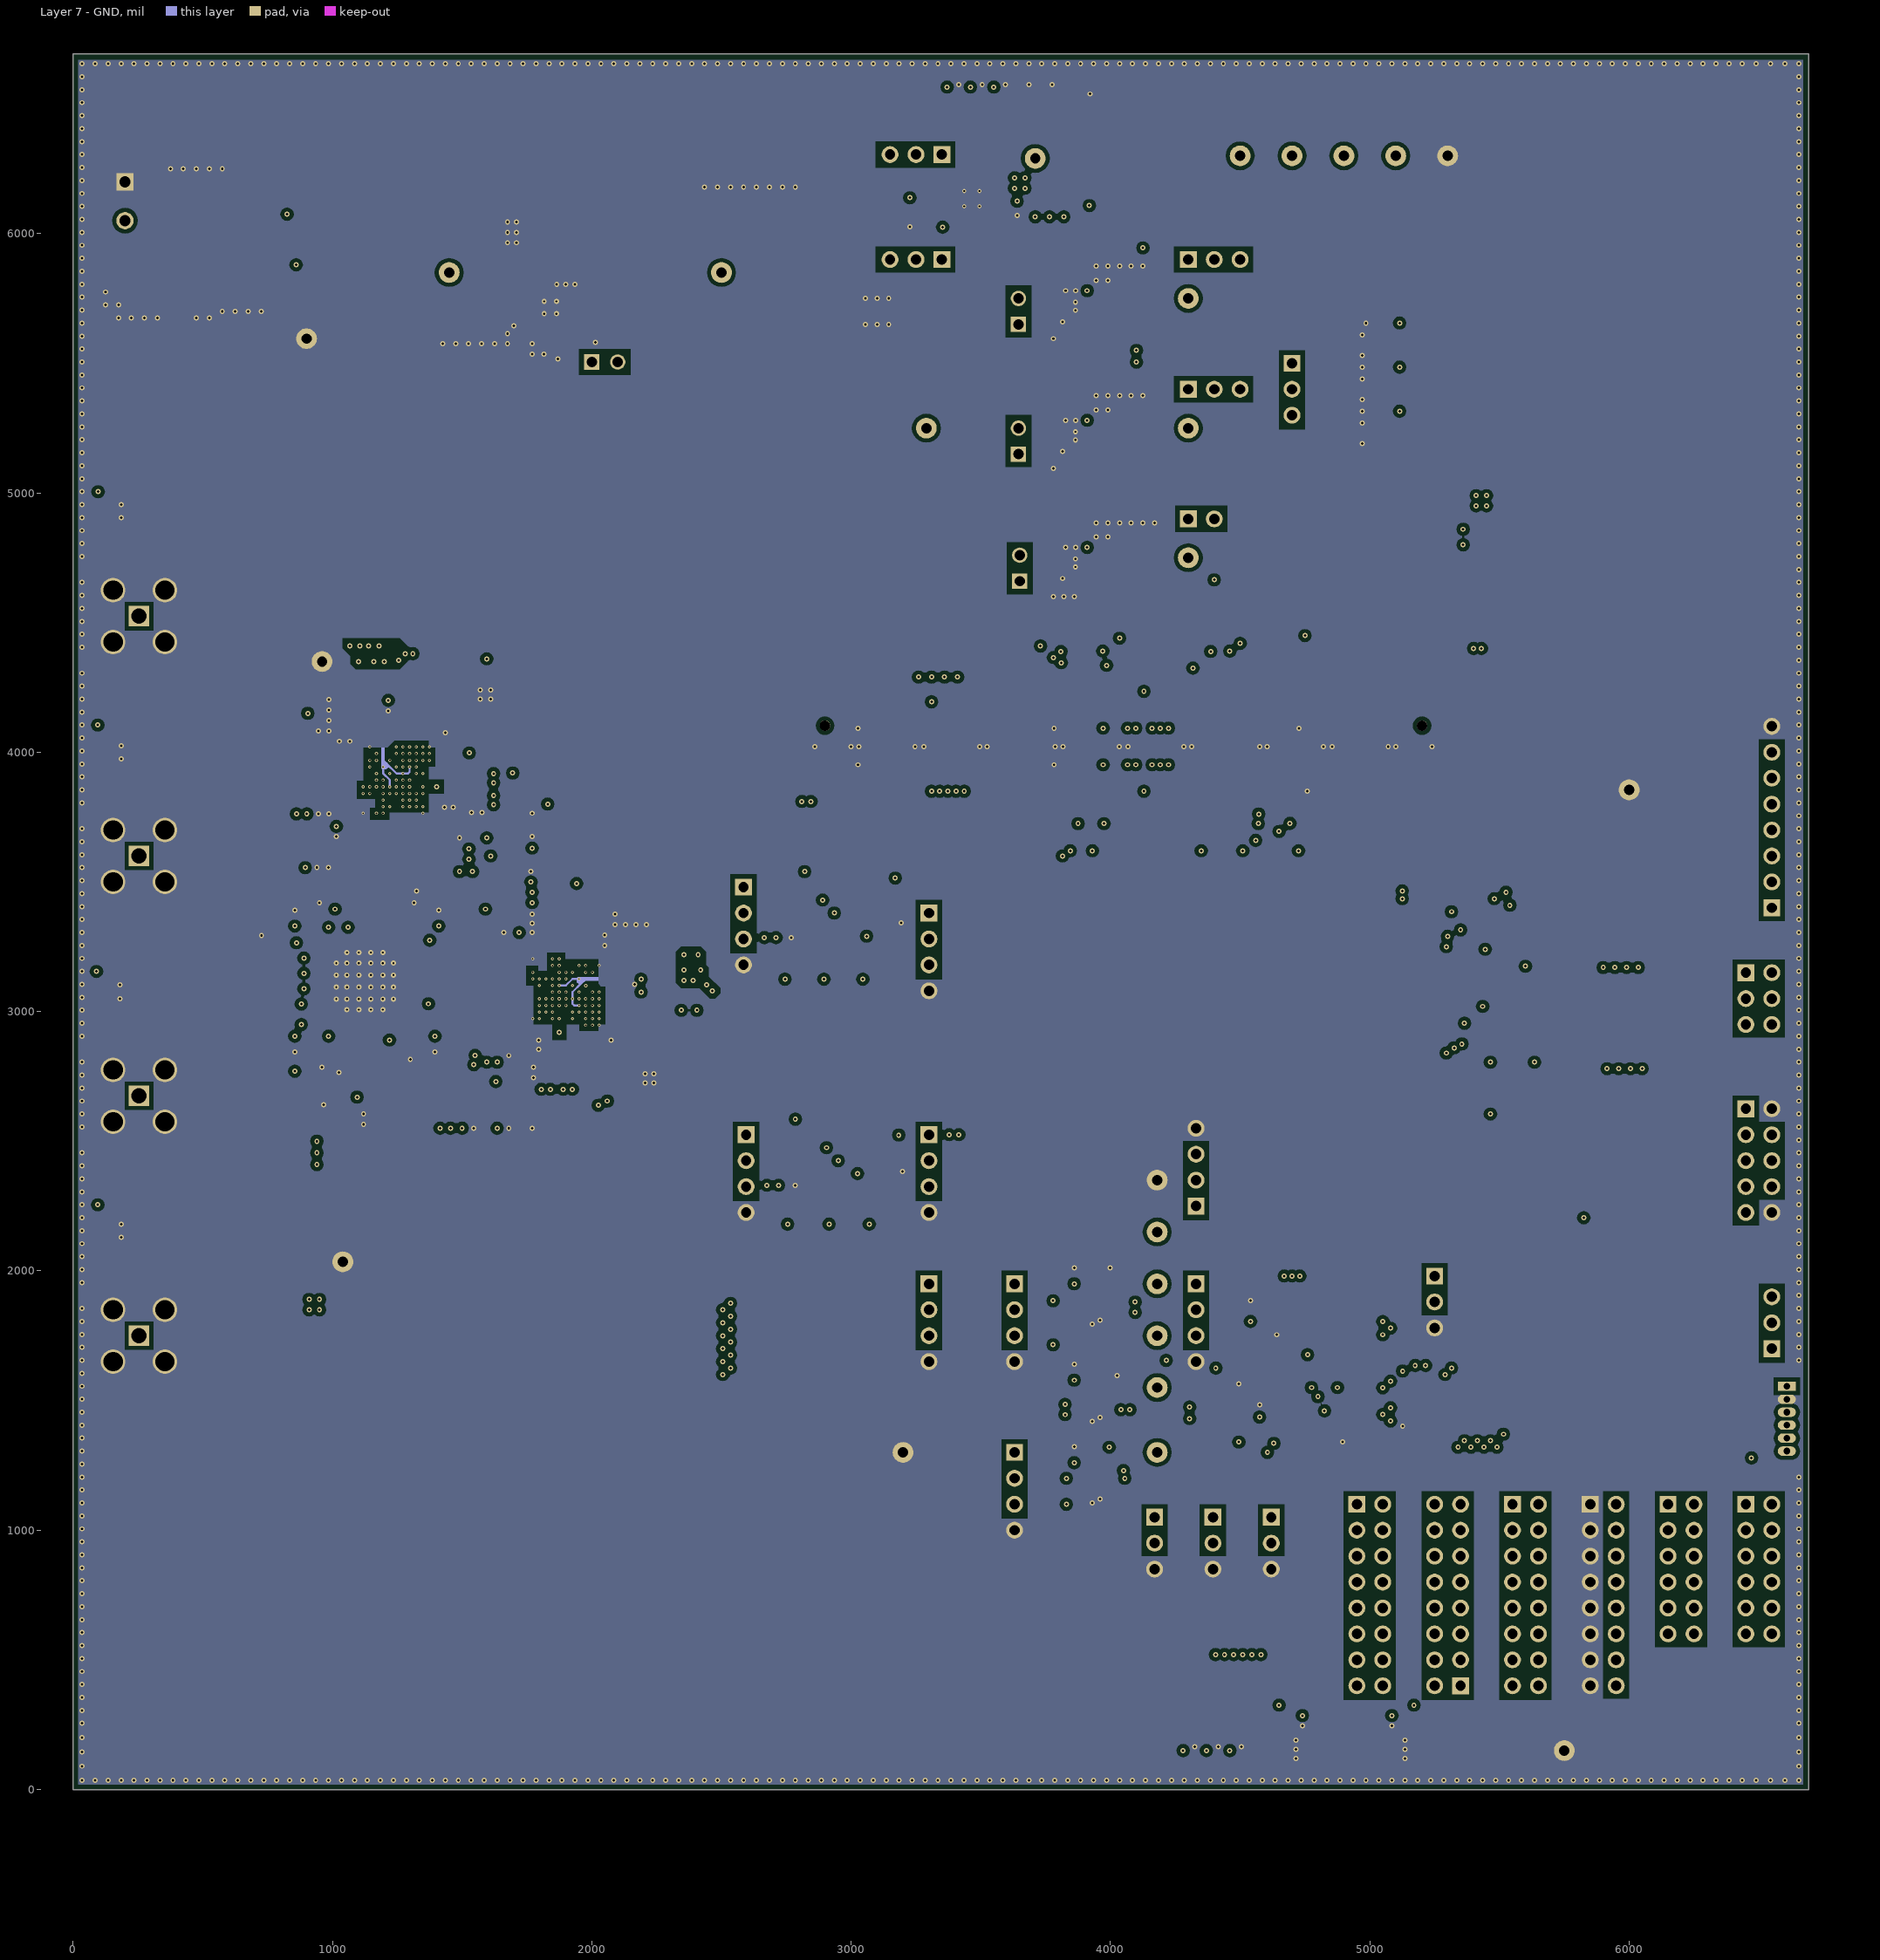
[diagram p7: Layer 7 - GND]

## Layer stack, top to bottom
Top Solder: solder mask 0.4, Solder Resist, Dk 3.5
Layer 1 - Top Layer: signal copper 1.4
Dielectric 1: prepreg 5.91, 370HR, Dk 4.2
Layer 2 - GND: signal copper 1.417
Dielectric 2: core 5, 370HR, Dk 4.2
Layer 3 - Sensitive: signal copper 1.417
Dielectric 3: prepreg 5, 370HR, Dk 4.2
Layer 4 - GND: signal copper 1.417
Dielectric 4: core 20, 370HR, Dk 4.2
Layer 5 - PWR: signal copper 1.417
Dielectric 5: prepreg 5, 370HR, Dk 4.2
Layer 6 - Signal: signal copper 1.417
Dielectric 6: core 5, 370HR, Dk 4.2
Layer 7 - GND: signal copper 1.417
Dielectric 7: prepreg 5.91, 370HR, Dk 4.2
Layer 8 - Bottom Layer: signal copper 1.4
Bottom Solder: solder mask 0.4, Solder Resist, Dk 3.5

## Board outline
0,0 6693,0 6693,6693.1 0,6693.1

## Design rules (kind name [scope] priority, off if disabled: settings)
AcuteAngle [All] p1: minimum=4.50000000000000E+0001 checktracksonly=FALSE
AssemblyTestPointUsage [All] p1: valid=2
Clearance Clearance_Keepouts [((IsTrack Or IsArc) And Not InPoly) And IsFree and IsKeepOut vs ((IsTrack Or IsArc) And Not InPoly) And IsFree and IsKeepOut] p1: gap=0
Clearance Clearance_BoardEdge_MountingHoles [OnCopper and InComponentClass('Mounting Holes') vs IsKeepOut] p2: gap=30
Clearance Clearance_BoardEdge_Poly [OnCopper and InPoly vs IsKeepOut] p3: gap=25
Clearance Clearance_BoardEdge [OnCopper and Not InComponentClass('Logo') and not InComponentClass('FiducialMark') and not InRegion(1000,500,4000,800) and Not IsKeepout vs IsKeepOut] p4: gap=75
Clearance Clearance_Poly [InPolygon] p5: gap=15
Clearance [All] p6: gap=4
ComponentClearance ComponentClearance_MountingHoles_FiducialMarks [InComponentClass('Mounting Holes') vs InComponentClass('FiducialMark')] p1 off: gap=50 collisioncheckmode=3 verticalgap=10 showdistances=FALSE
ComponentClearance ComponentClearance_Shunt [InComponentClass('Header') vs InComponentClass('Shunt')] p2 off: gap=0 collisioncheckmode=3 verticalgap=0 showdistances=FALSE
ComponentClearance ComponentClearance_Logo [InComponentClass('Logo')] p3 off: gap=50 collisioncheckmode=3 verticalgap=10 showdistances=FALSE
ComponentClearance ComponentClearance_ScrewToNut [(HasFootprint('NY PMS 440 0025 PH')) vs (HasFootprint('Keystone_1902C'))] p4 off: gap=5 collisioncheckmode=3 verticalgap=10 showdistances=FALSE
ComponentClearance ComponentClearance_MountingHoles [InComponentClass('Mounting Holes')] p5 off: gap=250 collisioncheckmode=3 verticalgap=100000 showdistances=FALSE
ComponentClearance ComponentClearance_SmallPassives [HasFootprint('0201*') or HasFootprint('0402*') or HasFootprint('0508') or HasFootprint('0603*') or HasFootprint('0612') or HasFootprint('0805*') or HasFootprint('0815*') or HasFootprint('0830*') or HasFootprint('1206*') or HasFootprint('1210*') or HasFootprint('1808*') or HasFootprint('1812*') or HasFootprint('1825*') or HasFootprint('2010*') or HasFootprint('2220*') or HasFootprint('2225*') or HasFootprint('2512*') or HasFootprint('2728*') or HasFootprint('3518*') vs HasFootprint('0201*') or HasFootprint('0402*') or HasFootprint('0508') or HasFootprint('0603*') or HasFootprint('0612') or HasFootprint('0805*') or HasFootprint('0815*') or HasFootprint('0830*') or HasFootprint('1206*') or HasFootprint('1210*') or HasFootprint('1808*') or HasFootprint('1812*') or HasFootprint('1825*') or HasFootprint('2010*') or HasFootprint('2220*') or HasFootprint('2225*') or HasFootprint('2512*') or HasFootprint('2728*') or HasFootprint('3518*')] p6 off: gap=20 collisioncheckmode=3 verticalgap=10 showdistances=FALSE
ComponentClearance ComponentClearance_THtoSMT [IsThruComponent vs IsSMTComponent] p7 off: gap=100 collisioncheckmode=3 verticalgap=30 showdistances=FALSE
ComponentClearance ComponentClearance_THtoTH [IsThruComponent vs IsThruComponent] p8 off: gap=118.11 collisioncheckmode=3 verticalgap=30 showdistances=FALSE
ComponentClearance [All] p9 off: gap=40 collisioncheckmode=3 verticalgap=10 showdistances=FALSE
DiffPairsRouting [All] p1: maxlimit=100 minlimit=5.5 mostfreqgap=10 toplayer_maxgap=10 toplayer_prefgap=5.5 toplayer_minwidth=5 toplayer_maxwidth=5 toplayer_prefwidth=5 midlayer1_maxgap=10 midlayer1_prefgap=5.5 midlayer1_minwidth=5 midlayer1_maxwidth=5 midlayer1_prefwidth=5 midlayer2_maxgap=10 midlayer2_prefgap=5.5 midlayer2_minwidth=5 midlayer2_maxwidth=5 midlayer2_prefwidth=5 midlayer3_maxgap=10 midlayer3_prefgap=5.5 midlayer3_minwidth=5 midlayer3_maxwidth=5 midlayer3_prefwidth=5 midlayer4_maxgap=10 midlayer4_prefgap=5.5 midlayer4_minwidth=5 midlayer4_maxwidth=5 midlayer4_prefwidth=5 midlayer5_mingap=10 midlayer5_minwidth=15 midlayer5_maxwidth=15 midlayer5_prefwidth=15 midlayer6_mingap=10 midlayer6_minwidth=15 midlayer6_maxwidth=15 midlayer6_prefwidth=15 bottomlayer_maxgap=10 bottomlayer_prefgap=5.5 bottomlayer_minwidth=5 bottomlayer_maxwidth=5 bottomlayer_prefwidth=5 maxuncoupledlength=1000
FabricationTestPointUsage TestPointUsage [All] p1: valid=2 allowmultiple=FALSE
FabricationTestpoint Testpoint [All] p1: side=3 testpointundercomponent=TRUE minsize=40 maxsize=100 preferedsize=60 minholesize=0 maxholesize=40 preferedholesize=32 testpointgrid=1 allowsidetop=TRUE allowsidebottom=TRUE usegrid=TRUE gridtolerance=0.01
FanoutControl Fanout_LCC [IsLCC] p1: bgadir=Out bgaviamode=Centered fanoutstyle=Auto fanoutdirection=Alternating viagrid=1 // Fanout_LCC (Default Rule)
FanoutControl Fanout_BGA [IsBGA] p2: bgadir=Out bgaviamode=Centered fanoutstyle=Auto fanoutdirection=Alternating viagrid=1 // Fanout_BGA (Default Rule)
FanoutControl Fanout_Default [All] p4: bgadir=Out bgaviamode=Centered fanoutstyle=Auto fanoutdirection=Alternating viagrid=1 // Fanout_Default (Default Rule)
FanoutControl Fanout_Small [(CompPinCount < 5)] p5: bgadir=Out bgaviamode=Centered fanoutstyle=Auto fanoutdirection=OutThenIn viagrid=1 // Fanout_Small (Default Rule)
HoleSize [All] p1: absolutevalues=TRUE maxlimit=251 minlimit=6 maxpercent=80.000 minpercent=20.000
MinimumAnnularRing MinimumAnnularRing_ThermalPadVias [IsVia and InAnyComponent] p1: minimumring=3.94
MinimumAnnularRing [All] p2: minimumring=3
MinimumSolderMaskSliver MinimumSolderMaskSliver_Logo [InComponentClass('Logo') vs InComponentClass('Logo')] p1: minsoldermaskwidth=0.7
MinimumSolderMaskSliver [All] p2: minsoldermaskwidth=3.94
PlaneConnect [All] p1: planeconnectstyle=Relief reliefexpansion=10 reliefentries=4 reliefconductorwidth=10 reliefairgap=10
PolygonConnect [All] p1: connectstyle=Direct reliefconductorwidth=10 reliefentries=4 polygonreliefangle="90 Angle" airgapwidth=10
RoutingVias ThermalPadVias [IsVia and InAnyComponent] p1: holewidth=7.87 width=19.68 viastyle="Through Hole" minholewidth=7.87 minwidth=15.75 maxholewidth=12.99 maxwidth=23.62
RoutingVias [All] p2: holewidth=16 width=34 viastyle="Through Hole" minholewidth=6 minwidth=12 maxholewidth=40 maxwidth=65
SilkToBoardRegionClearance [Not ((IsComment or IsDesignator) And (Hide <> 'False')) and not InRegion(1000,500,4000,800)] p1:
SilkToSilkClearance SilkToSilkClearance_Pb-FreeLogo [(HasFootprint('Pb-Free_Overlay_Medium') OR HasFootprint('Pb-Free_Overlay_Small')) vs (HasFootprint('Pb-Free_Overlay_Medium') OR HasFootprint('Pb-Free_Overlay_Small'))] p1: silktosilkclearance=0
SilkToSilkClearance [All] p2: silktosilkclearance=3
SilkToSolderMaskClearance "Silk to Solder Mask Opening" [All] p1: minsilkscreentomaskgap=1 clearancetoexposedcopper=FALSE
SolderMaskExpansion [All] p1: expansion=1.97
UnpouredPolygon [All] p1: allowunpoured=FALSE
Width [All] p1: maxlimit=100 minlimit=5 preferedwidth=10 midlayer5_minwidth=5.5 midlayer6_minwidth=6 minimp=50.000000 maximp=50.000000 favimp=50.000000 checkconnectedcopper=TRUE
14 further rules are at their usual default settings.

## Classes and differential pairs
component class OV490_2: C135 C136 C137 C138 C139 C140 C141 C142 C143 C144 C145 C146 C147 C148 C149 C150 C151 C152 C153 C154 C162 J17 J18 L34 L35 L36 R74 R86 R87 R88 R89 R90 R91 R92 R93 R94 R95 R96 R97 R98 R99 R100 R101 R103 R105 R106 R107 R108 R109 R110 R111 R112 R113 R114 R115 R137 R138 R139 R160 R161 R162 TP21 TP22 TP23 TP29 TP30 TP31 TP32 TP42 TP47 TP48 TP49 TP50 U12 U14 Y3
component class AssemblyNote: ZZ1 ZZ2 ZZ3
component class FiducialMark: FID1 FID2 FID3 FID4 FID5 FID6
component class Hardware: FID1 FID2 FID3 FID4 FID5 FID6 Logo1 Logo2 ZZ1 ZZ2 ZZ3
component class Logo: Logo1
component class cam_connections: C1 C2 C3 C4 C5 C6 C7 C8 C9 C10 C11 C12 C13 C14 C15 C16 C17 C18 C19 C20 C21 C22 C23 C24 C25 C26 C27 C28 J1 J2 J3 J4 J41 J42 L1 L2 L3 L4 L5 L6 L7 L8 L9 L10 L11 L12 L13 L14 L15 L16 R1 R2 R3 R4 R5 R6 R7 R8 R9 R10 R11 R12 R13 R14 R15 R16 TP1 TP2 TP3 TP4
component class Deserializer: C54 C56 C57 C58 C60 C61 C62 C63 C64 C65 C66 C69 C70 C71 C72 C76 C77 C78 C79 C84 C85 C86 C90 C91 C92 C94 C95 C96 C97 C100 C101 C102 C103 C106 C107 C108 C111 C112 C113 C114 L21 L22 L23 L27 L28 L30 R45 R46 R47 R48 R49 R51 R52 R53 R54 R55 R154 R155 TP16 TP17 U1 Y1
component class Header: J6 J7 J8 J9 J10 J11 J12 J13 J14 J15 J16 J17 J18 J19 J20 J21 J22 J24 J25 J26 J27 J28 J30 J31 J32 J33 J34 J35 J36 J37 J38 J39 J40
component class OV490_1: C115 C116 C117 C118 C119 C120 C121 C122 C123 C124 C125 C126 C127 C128 C129 C130 C131 C132 C133 C134 C160 J14 J16 L31 L32 L33 R56 R57 R58 R59 R60 R61 R62 R63 R64 R65 R66 R67 R68 R69 R70 R71 R72 R73 R75 R76 R77 R78 R79 R80 R81 R82 R83 R84 R85 R133 R134 R136 R157 R158 R159 TP18 TP19 TP20 TP33 TP34 TP35 TP36 TP37 TP38 TP39 TP40 TP41 U8 U10 Y2
component class V_Batt_Supply: 1 2 3 4 5 6 7 8 C29 C30 C31 C32 C33 C34 C35 C36 C37 C38 C39 C40 C41 C42 C43 D1 D2 D3 D6 D7 J5 J13 L17 M1 Q1 Q2 R17 R18 R19 R20 R21 R22 R23 R24 R25 R26 R27 R28 R29 R30 R31 R50 R117 R125 TP5 TP6 U2 U20
component class Camera_Switch_and_Bucks: C44 C45 C46 C47 C48 C49 C50 C51 C52 C53 C75 C163 C164 D8 D9 D10 D11 F1 J6 J7 J8 J9 J10 J11 J12 J15 J30 L18 L19 L20 R32 R33 R34 R35 R36 R37 R38 R39 R40 R41 R42 R43 R44 R127 R129 R130 R131 R132 R140 R184 R185 R201 R204 TP7 TP8 TP9 TP10 TP11 TP12 TP13 TP14 TP15 TP43 TP44 TP45 TP46 U3 U4 U5 U6 U7 U21 U23
component class TDA2x_Conector: J25 J29 J31 J32 J40 R151 R152 R174 R175 R176 R177 R178 R179 R180 R181 R182 R186 R187 R188 R189 R190 R191 R192 R193 R194 R195 R196 R197 R198 R199 R200 R202 R203 R205 R206 R207 R208 R209 R210 R211 R212 R213 R214 R215 R216 R217 R218 R219 R220 R221 R222 R223 R224
component class uC: C80 C155 C156 C157 C158 C159 C161 D4 D5 D12 J19 J20 J21 J22 J23 J24 J26 J27 J28 J33 J34 J35 J36 J37 J38 J39 R102 R104 R116 R118 R119 R120 R121 R122 R123 R124 R126 R128 R135 R141 R142 R143 R144 R145 R146 R147 R148 R149 R150 R153 R156 R163 R164 R165 R166 R167 R168 R171 R172 R173 S1 S2 TP24 TP25 TP26 TP27 TP28 U16 U17 U18 U19
differential pair CSI0_CLK: +CSI0_CLK_P -CSI0_CLK_N
differential pair CSI0_D0: +CSI0_D0_P -CSI0_D0_N
differential pair CSI0_D1: +CSI0_D1_P -CSI0_D1_N
differential pair CSI0_D2: +CSI0_D2_P -CSI0_D2_N
differential pair CSI0_D3: +CSI0_D3_P -CSI0_D3_N
differential pair CSI1_CLK: +CSI1_CLK_P -CSI1_CLK_N
differential pair CSI1_D0: +CSI1_D0_P -CSI1_D0_N
differential pair CSI1_D1: +CSI1_D1_P -CSI1_D1_N
differential pair CSI1_D2: +CSI1_D2_P -CSI1_D2_N
differential pair CSI1_D3: +CSI1_D3_P -CSI1_D3_N
differential pair LPTX: +LPTX_P -LPTX_N
differential pair RIN0: +RIN0_P -RIN0_N
differential pair RIN1: +RIN1_P -RIN1_N
differential pair RIN2: +RIN2_P -RIN2_N
differential pair RIN3: +RIN3_P -RIN3_N

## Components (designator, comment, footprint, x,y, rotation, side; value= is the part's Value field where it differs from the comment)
C1 "C1005X7R1H104K050BB" 0402 120,4805 r180 top
C2 "GRM188R61E475KE11D" 0603L 120,4755 r180 top
C3 "C1005X7R1H104K050BB" 0402 120,4955 r0 top
C4 "GRM188R61E475KE11D" 0603L 120,4905 r0 top
C5 "C1005X7R1H104K050BB" 0402 120,3875 r180 top
C6 "GRM188R61E475KE11D" 0603L 117.8,3822.8 r180 top
C7 "C1005X7R1H104K050BB" 0402 120,4025 r0 top
C8 "GRM188R61E475KE11D" 0603L 120,3975 r0 top
C9 "CGA2B3X7R1H333K050BB" 0402 520,4525 r180 top
C10 "CGA2B3X7R1H333K050BB" 0402 520,3600 r180 top
C11 "CGA2B3X7R1H153K050BB" 0402 520,4485 r0 top
C12 "CGA2B3X7R1H153K050BB" 0402 520,3560 r0 top
C13 "GRM1555C1H241JA01D" 0402 460,4300 r90 top
C14 "GRM1555C1H241JA01D" 0402 460,3375 r90 top
C15 "C1005X7R1H104K050BB" 0402 120,2950 r180 top
C16 "GRM188R61E475KE11D" 0603L 115,2900 r180 top
C17 "C1005X7R1H104K050BB" 0402 115,3102.5 r0 top
C18 "GRM188R61E475KE11D" 0603L 115,3050 r0 top
C19 "C1005X7R1H104K050BB" 0402 120,2030 r180 top
C20 "GRM188R61E475KE11D" 0603L 115,1980 r180 top
C21 "C1005X7R1H104K050BB" 0402 120,2180 r0 top
C22 "GRM188R61E475KE11D" 0603L 120,2130 r0 top
C23 "CGA2B3X7R1H333K050BB" 0402 520,2675 r180 top
C24 "CGA2B3X7R1H333K050BB" 0402 520,1750 r180 top
C25 "CGA2B3X7R1H153K050BB" 0402 520,2635 r0 top
C26 "CGA2B3X7R1H153K050BB" 0402 520,1710 r0 top
C27 "GRM1555C1H241JA01D" 0402 460,2450 r90 top
C28 "GRM1555C1H241JA01D" 0402 460,1525 r90 top
C29 "C1608X7R1H104K" 0603 1070,5905 r270 top
C30 "GRM32ER72A225KA35L" 1210 425,6130 r270 top
C31 "GRM32ER72A225KA35L" 1210 550,6130 r270 top
C32 "C1608X7R1H104K" 0603 565,5775 r270 top
C33 "C3216X7R1E475M" 1206 2110,6065 r270 top
C34 "C3216X7R1E475M" 1206 2470,6065 r90 top
C35 "C3216X7R1E475M" 1206 2565,6065 r90 top
C36 "C3216X7R1E475M" 1206 2660,6065 r90 top
C37 "GRM155R70J104KA01D" 0402 1700,5715 r270 top
C38 "GRM31CR71E106KA12L" 1206 1515,5690 r270 top
C39 "GRM31CR71E106KA12L" 1206 1420,5690 r270 top
C40 "GRM31CR71E106KA12L" 1206 1610,5690 r270 top
C41 "GRM155R70J473KA01D" 0402 1790,5615 r0 top
C42 "CC0402KRX7R9BB101" 0402 1840,5570 r180 top
C43 "GRM155R71C103KA01D" 0402 1910,5540 r270 top
C44 "GRM31CR71C106KAC7L" 1206 3835,5850 r0 top
C45 "GRM31CR61C226KE15L" 1206 4060,5755 r90 top
C46 "" 1206 4155,5755 r90 top
C47 "EEE-FK1E470P" SM_RADIAL_D 3200,5700 r180 top
C48 "GRM31CR71C106KAC7L" 1206 3835,5350 r0 top
C49 "GRM31CR61C226KE15L" 1206 4060,5255 r90 top
C50 "" 1206 4155,5255 r90 top
C51 "GRM31CR71C106KAC7L" 1206 3830,4860 r0 top
C52 "GRM31CR61C226KE15L" 1206 4060,4765 r90 top
C53 "" 1206 4155,4765 r90 top
C54 "CL21A106KAFN3NE" 0805_HV 1500,3395 r180 bottom
C56 "C1005JB1V105K050BC" 0402 1450,3300 r90 bottom
C57 "CGA2B3X7R1H104K050BB" 0603 1310,3225 r180 bottom
C58 "GCM155R71H103KA55D" 0402 1305,3275 r180 bottom
C60 "CL21A106KAFN3NE" 0805_HV 955,2845 r0 bottom
C61 "C1005JB1V105K050BC" 0402 815,2930 r270 bottom
C62 "CGA2B3X7R1H104K050BB" 0603 930,3270 r0 bottom
C63 "GCM155R71H103KA55D" 0402 950,3175 r0 bottom
C64 "GCM155R71H103KA55D" 0402 950,2941 r0 bottom
C65 "GCM155R71H103KA55D" 0402 950,3085 r0 bottom
C66 "GCM155R71H103KA55D" 0402 950,3130 r0 bottom
C69 "C1005JB1V105K050BC" 0402 895,3360 r90 bottom
C70 "CGA2B3X7R1H104K050BB" 0603 895,3360 r90 top
C71 "GCM155R71H103KA55D" 0402 950,3360 r90 top
C72 "C1005X7R1H104M" 0402 985,3490 r90 top
C75 "C1005JB1V105K050BC" 0402 5050,5655 r180 top
C76 "CGA2B3X7R1H104K050BB" 0603 1020,3305 r270 bottom
C77 "GCM155R71H103KA55D" 0402 950,3360 r90 bottom
C78 "CGA2B3X7R1H333K050BB" 0402 824.36,3137.64 r180 top
C79 "CGA2B3X7R1H333K050BB" 0402 824.36,3097.64 r180 top
C80 "UMK105B7222KV-F" 0402 5150,245 r180 top
C84 "CGA2B3X7R1H104K050BB" 0603 895,2875 r270 top
C85 "GCM155R71H103KA55D" 0402 950,2875 r270 top
C86 "C1005X7R1H104M" 0402 985,3490 r90 bottom
C90 "CGA2B3X7R1H104K050BB" 0603 1080,2930 r90 bottom
C91 "GCM155R71H103KA55D" 0402 1030,2935 r90 bottom
C92 "CL21A106KAFN3NE" 0805_HV 1255,3435 r90 bottom
C94 "C1005JB1V105K050BC" 0402 1150,3300 r270 bottom
C95 "CGA2B3X7R1H104K050BB" 0603 1100,3305 r270 bottom
C96 "GCM155R71H103KA55D" 0402 1185,2935 r90 bottom
C97 "GCM155R71H103KA55D" 0402 1255,2935 r90 bottom
C100 "C1005JB1V105K050BC" 0402 1315,3360 r90 bottom
C101 "CGA2B3X7R1H104K050BB" 0603 1370,3360 r90 top
C102 "GCM155R71H103KA55D" 0402 1305,3030 r180 bottom
C103 "GCM155R71H103KA55D" 0402 1315,3360 r90 top
C106 "C1005JB1V105K050BC" 0402 1300,2875 r270 bottom
C107 "CGA2B3X7R1H104K050BB" 0603 1355,2875 r270 top
C108 "GCM155R71H103KA55D" 0402 1300,2875 r270 top
C111 "C1005JB1V105K050BC" 0402 750,3260 r180 bottom
C112 "CGA2B3X7R1H104K050BB" 0603 945,2990 r0 bottom
C113 "GCM155R71H103KA55D" 0402 950,3040 r0 bottom
C114 "GCM155R71H103KA55D" 0402 950,3220 r0 bottom
C115 "C1005X7R1H104K050BB" 0402 1855,3245 r180 bottom
C116 "C2012X7R0J106M125AB" 0805 1855,3360 r180 bottom
C117 "C0603C225M8PACTU" 0603 1855,3295 r180 bottom
C118 "C1005X5R1A474K050BB" 0402 1980,3290 r180 bottom
C119 "C2012X7R0J106M125AB" 0805 2000,3350 r180 bottom
C120 "C1005X5R1A474K050BB" 0402 2135,3275 r270 top
C121 "C1005X5R1A475K050BC" 0402 2180,3275 r270 top
C122 "C1005X7R1H104K050BB" 0402 1980,3245 r180 bottom
C123 "C2012X5R1A225K/0.85" 0805 1965,3305 r180 top
C124 "C1005X7R1H104K050BB" 0402 1965,3245 r180 top
C125 "C2012X7R0J106M125AB" 0805 1870,2770 r180 bottom
C126 "C1005X7R1H104K050BB" 0402 1870,2880 r180 bottom
C127 "C1005X7R1H104K050BB" 0402 1870,2835 r0 bottom
C128 "GRM1885C2A180JA01D" 0603 2125,2760 r0 bottom
C129 "C1005X7R1H104K050BB" 0402 1680,2895 r270 top
C130 "C1005X7R1H104K050BB" 0402 1870,2880 r180 top
C131 "C1005X7R1H104K050BB" 0402 1695,3175 r180 bottom
C132 "C0603C105K4PACTU" 0603 1690,3225 r0 bottom
C133 "C0603C105K4PACTU" 0603 1870,2830 r0 top
C134 "GRM1885C2A180JA01D" 0603 2225,2850 r270 bottom
C135 "C1005X7R1H104K050BB" 0402 1075,3850 r270 bottom
C136 "C2012X7R0J106M125AB" 0805 960,3850 r270 bottom
C137 "C0603C225M8PACTU" 0603 1025,3845 r270 bottom
C138 "C1005X5R1A474K050BB" 0402 1035,3975 r270 bottom
C139 "C2012X7R0J106M125AB" 0805 975,3990 r270 bottom
C140 "C1005X5R1A474K050BB" 0402 1045,4130 r0 top
C141 "C1005X5R1A475K050BC" 0402 1045,4175 r0 top
C142 "C1005X7R1H104K050BB" 0402 1075,3975 r270 bottom
C143 "C2012X5R1A225K/0.85" 0805 1015,3960 r270 top
C144 "C1005X7R1H104K050BB" 0402 1075,3960 r270 top
C145 "C2012X7R0J106M125AB" 0805 1555,3865 r270 bottom
C146 "C1005X7R1H104K050BB" 0402 1485,3860 r270 bottom
C147 "C1005X7R1H104K050BB" 0402 1440,3860 r90 bottom
C148 "GRM1885C2A180JA01D" 0603 1565,4130 r90 bottom
C149 "C1005X7R1H104K050BB" 0402 1425,3670 r0 top
C150 "C1005X7R1H104K050BB" 0402 1440,3865 r270 top
C151 "C1005X7R1H104K050BB" 0402 1146,3685 r270 bottom
C152 "C0603C105K4PACTU" 0603 1095,3685 r90 bottom
C153 "C0603C105K4PACTU" 0603 1490,3860 r90 top
C154 "GRM1885C2A180JA01D" 0603 1470,4215 r0 bottom
C155 "UMK105B7222KV-F" 0402 4675,245 r0 top
C156 "LMK212B7475KG-T" 0805_HV 4600,1845 r90 top
C157 "GRM155R70J104KA01D" 0402 4610,1460 r90 top
C158 "0603YC104JAT2A" 0603 3905,1610 r90 top
C159 "0603YC104JAT2A" 0603 3900,1290 r90 top
C160 "C1005X7R1H104K050BB" 0402 2090,3275 r270 top
C161 "0603YC104JAT2A" 0603 3900,1980 r90 top
C162 "C1005X7R1H104K050BB" 0402 1045,4085 r0 top
C163 "C1005JB1V105K050BC" 0402 5050,5485 r180 top
C164 "C1005JB1V105K050BC" 0402 5050,5315 r180 top
D1 "MMSZ5245B-7-F" SOD-123 935,5895 r270 top
D2 "MMSZ5245B-7-F" SOD-123 485,5785 r270 top
D3 "B360-13-F" SMC 2290,6065 r90 top
D4 "SML-P12YTT86" LED_SMLP12_Yellow 4325,215 r270 top
D5 "SML-P12DTT86" LED_SMLP12_ORANGE 4415,215 r270 top
D6 "SML-P12UTT86" SML-P1_RED 3370,6515 r270 top
D7 "SML-P12PTT86" SML-P1_GREEN 3460,6515 r90 top
D8 "SML-P12DTT86" LED_SMLP12_ORANGE 3550,6515 r270 top
D9 "SML-P12MTT86" SML-P1_YELLOW-GREEN 3830,6515 r270 top
D10 "SML-P12YTT86" LED_SMLP12_Yellow 3730,6515 r270 top
D11 "SML-P12PTT86" SML-P1_GREEN 3640,6515 r90 top
D12 "SML-P12PTT86" SML-P1_GREEN 4505,215 r90 top
FID1 "Fiducial" Fiducial10-20 400,6500 r0 top
FID2 "Fiducial" Fiducial10-20 400,200 r0 top
FID3 "Fiducial" Fiducial10-20 6100,200 r0 top
FID4 "Fiducial" Fiducial10-20 400,200 r180 bottom
FID5 "Fiducial" Fiducial10-20 400,6500 r180 bottom
FID6 "Fiducial" Fiducial10-20 6100,200 r180 bottom
J1 "59S20X-400L5-Y" Rosenberger_59S20X-400L5 75,4525 r180 top
J2 "59S20X-400L5-Y" Rosenberger_59S20X-400L5 75,3600 r180 top
J3 "59S20X-400L5-Y" Rosenberger_59S20X-400L5 75,2675 r180 top
J4 "59S20X-400L5-Y" Rosenberger_59S20X-400L5 75,1750 r180 top
J5 "1727010" PhoenixConact_1727010 200,6125 r270 top
J6 "TSW-103-07-G-S" TSW-103-07-G-S 3250,6305 r180 top
J7 "TSW-103-07-G-S" TSW-103-07-G-S 4400,5900 r0 top
J8 "TSW-103-07-G-S" TSW-103-07-G-S 3250,5900 r180 top
J9 "PEC02SAAN" CONN_PEC02SAAN 3645,5700 r90 top
J10 "TSW-103-07-G-S" TSW-103-07-G-S 4400,5400 r0 top
J11 "TSW-103-07-G-S" TSW-103-07-G-S 4700,5400 r270 top
J12 "TSW-102-07-G-S" TSW-102-07-G-S 4350,4900 r0 top
J13 "PEC02SAAN" CONN_PEC02SAAN 2050,5505 r0 top
J14 "TSW-104-07-G-S" TSW-104-07-G-S 2595,2375 r270 top
J15 "PEC02SAAN" CONN_PEC02SAAN 3650,4710 r90 top
J16 "TSW-104-07-G-S" TSW-104-07-G-S 3300,2375 r270 top
J17 "TSW-104-07-G-S" TSW-104-07-G-S 2585,3330 r270 top
J18 "TSW-104-07-G-S" TSW-104-07-G-S 3300,3230 r270 top
J19 "TSW-103-07-G-S" TSW-103-07-G-S 5250,1880 r270 top
J20 "TSW-104-07-G-S" TSW-104-07-G-S 3630,1800 r270 top
J21 "TSW-104-07-G-S" TSW-104-07-G-S 4330,1800 r270 top
J22 "TSW-104-07-G-S" TSW-104-07-G-S 3300,1800 r270 top
J23 "851-43-006-20-001000" CONN_851-43-006-20-001000 6608,1430 r90 top
J24 "TSW-104-07-G-S" TSW-104-07-G-S 4330,2400 r90 top
J25 "TSW-105-07-G-D" TSW-105-07-G-D 6500,2425 r270 top
J26 "TSW-103-07-G-S" TSW-103-07-G-S 4395,950 r270 top
J27 "TSW-104-07-G-S" TSW-104-07-G-S 3630,1150 r270 top
J28 "TSW-108-07-G-D" TSW-108-07-G-D 5000,750 r270 top
J29 "QTE-060-01-F-D-A" Samtec_QTE-060-01-x-D-A 4050.38,4022.15 r180 bottom locked
J30 "PEC02SAAN" CONN_PEC02SAAN 3645,5200 r90 top
J31 "TSW-103-07-G-D" TSW-103-07-G-D 6500,3050 r270 top
J32 "TSW-108-07-G-S" TSW-108-07-G-S 6550,3750 r90 top
J33 "TSW-108-07-G-D" TSW-108-07-G-D 5300,750 r90 top
J34 "TSW-106-07-G-D" TSW-106-07-G-D 6200,850 r270 top
J35 "TSW-106-07-G-D" TSW-106-07-G-D 6500,850 r270 top
J36 "TSW-103-07-G-S" TSW-103-07-G-S 4170,950 r270 top
J37 "TSW-108-07-G-D" TSW-108-07-G-D 5600,750 r270 top
J38 "TSW-108-07-G-D" TSW-108-07-G-D 5900,750 r270 top
J39 "TSW-103-07-G-S" TSW-103-07-G-S 4620,950 r270 top
J40 "TSW-103-07-G-S" TSW-103-07-G-S 6550,1800 r90 top
L1 "BLM18AG102SN1D" 0603L 120,4855 r180 top
L2 "BLM18AG102SN1D" 0603L 120,3925 r180 top
L3 "LQH3NPN100NG0" LQH3NP_G0 595,4680 r90 top
L4 "MSS7341T-104MLB" MSS7341 350,4875 r180 top
L5 "LQH3NPN100NG0" LQH3NP_G0 595,3750 r90 top
L6 "MSS7341T-104MLB" MSS7341 350,3950 r180 top
L7 "BLM15HG102SN1D" 0402 495,4605 r90 top
L8 "BLM15HG102SN1D" 0402 495,3680 r90 top
L9 "BLM18AG102SN1D" 0603L 115,3000 r180 top
L10 "BLM18AG102SN1D" 0603L 120,2080 r180 top
L11 "LQH3NPN100NG0" LQH3NP_G0 595,2830 r90 top
L12 "MSS7341T-104MLB" MSS7341 350,3025 r180 top
L13 "LQH3NPN100NG0" LQH3NP_G0 595,1905 r90 top
L14 "MSS7341T-104MLB" MSS7341 350,2100 r180 top
L15 "BLM15HG102SN1D" 0402 495,2755 r90 top
L16 "BLM15HG102SN1D" 0402 495,1830 r90 top
L17 "DRQ127-2R2-R" DRQ127 1770,6065 r0 top
L18 "VLS201610HBX-2R2M" VLS201610ET 3965,5720 r270 top
L19 "VLS201610HBX-2R2M" VLS201610ET 3965,5220 r270 top
L20 "VLS201610HBX-2R2M" VLS201610ET 3965,4730 r270 top
L21 "BLM18SG121TN1D" 0603 1500,3295 r270 bottom
L22 "BLM18SG121TN1D" 0603 765,2930 r90 bottom
L23 "BLM18SG121TN1D" 0603 845,3480 r270 bottom
L27 "BLM18SG121TN1D" 0603 1235,3330 r180 bottom
L28 "BLM18SG121TN1D" 0603 1370,3360 r270 bottom
L30 "BLM18SG121TN1D" 0603 750,3210 r0 bottom
L31 "BK2125HS102-T" 0805_HV 1855,3440 r180 bottom
L32 "BK2125HS102-T" 0805_HV 1965,3385 r0 top
L33 "BK2125HS102-T" 0805_HV 1615,2890 r270 top
L34 "BK2125HS102-T" 0805_HV 880,3850 r270 bottom
L35 "BK2125HS102-T" 0805_HV 935,3960 r90 top
L36 "BK2125HS102-T" 0805_HV 1440,3605 r0 top
Logo1 "Texas Instruments" TI_Stacked_SolderMask_Medium 3350,400 r0 top
Logo2 "Pb-Free Symbol" Pb-Free_Overlay_Small 4100,115 r0 top
M1 "SQ2360EES-T1-GE3" SOT-23 730,5775 r0 top
Q1 "SQJ461EP" PowerPAK_SO-8L 750,6000 r180 top
Q2 "SQJ461EP" PowerPAK_SO-8L 1240,5950 r0 top
R1 "CRCW06032K00FKEA" 0603 700,4680 r90 top
R2 "ERJ-3EKF1001V" 0603 350,5070 r180 top
R3 "CRCW06032K00FKEA" 0603 700,3750 r90 top
R4 "ERJ-3EKF1001V" 0603 350,4140 r180 top
R5 "CRCW040257R6FKED" 0402 385,4325 r0 top
R6 "CRCW040257R6FKED" 0402 385,3400 r0 top
R7 "CRCW0402200RJNED" 0402 385,4275 r0 top
R8 "CRCW0402200RJNED" 0402 385,3350 r0 top
R9 "CRCW06032K00FKEA" 0603 700,2830 r90 top
R10 "ERJ-3EKF1001V" 0603 350,3214 r180 top
R11 "CRCW06032K00FKEA" 0603 700,1905 r90 top
R12 "ERJ-3EKF1001V" 0603 350,2290 r180 top
R13 "CRCW040257R6FKED" 0402 385,2475 r0 top
R14 "CRCW040257R6FKED" 0402 385,1550 r0 top
R15 "CRCW0402200RJNED" 0402 385,2425 r0 top
R16 "CRCW0402200RJNED" 0402 385,1500 r0 top
R17 "CRCW20100000Z0EF" 2010 1330,6145 r0 top
R18 "ERJ-3EKF1003V" 0603 1015,5905 r270 top
R19 "RC0603FR-0720KL" 0603 830,5830 r0 top
R20 "RC0603FR-0720KL" 0603 305,5885 r90 top
R21 "CRCW060311K8FK" 0603 250,5885 r90 top
R22 "ERJ-3EKF1003V" 0603 620,5775 r270 top
R23 "CRCW06031K00FKEA" 0603 250,5765 r90 top
R24 "CRCW08050000Z0EA" 0805_HV 2935,6020 r0 top
R25 "CRCW1206100KJNEA" 1206 2755,6065 r270 top
R26 "CRCW040210K0JNED" 0402 1740,5715 r270 top
R27 "CRCW04022K32FKED" 0402 1890,5615 r180 top
R28 "CRCW040218K2FKED" 0402 1945,5730 r270 top
R29 "CRCW040249R9FKED" 0402 1990,5730 r270 top
R30 "CRCW040288K7FKED" 0402 1970,5660 r0 top
R31 "CRCW040210K0FKED" 0402 1990,5615 r0 top
R32 "CRCW06030000Z0EA" 0603 3710,6140 r90 top
R33 "CRCW06030000Z0EA" 0603 3765,6140 r90 top
R34 "CRCW06030000Z0EA" 0603 3820,6140 r90 top
R35 "CRCW06030000Z0EA" 0603 3875,6140 r90 top
R36 "CRCW0603100KFKEA" 0603 3860,5840 r180 bottom
R37 "CRCW0603316KFKEA" 0603 4010,5630 r0 top
R38 "CRCW0603100KFKEA" 0603 3890,5630 r0 top
R39 "CRCW0603100KFKEA" 0603 3865,5345 r0 bottom
R40 "CRCW0603124KFKEA" 0603 4010,5130 r0 top
R41 "CRCW0603100KFKEA" 0603 3890,5130 r0 top
R42 "CRCW0603100KFKEA" 0603 3860,4850 r0 bottom
R43 "CRCW060337K4FKEA" 0603 4010,4640 r0 top
R44 "CRCW0603100KFKEA" 0603 3890,4640 r0 top
R45 "CRCW040210K0JNED" 0402 1031.2,2400 r0 top
R46 "ERJ-2GE0R00X" 0402 1031.2,2670 r0 top
R47 "ERJ-2GE0R00X" 0402 1031.2,2715 r180 top
R48 "CRCW040213K3FKED" 0402 895,3490 r90 top
R49 "CRCW040240K2FKED" 0402 940,3490 r270 top
R50 "CRCW04022K20JNED" 0402 3415,6515 r270 top
R51 "CRCW0402100RFKED" 0402 755,3118 r90 top
R52 "ERJ-2GE0R00X" 0402 1090,2785 r270 top
R53 "CRCW040256K2FKED" 0402 895,3490 r90 bottom
R54 "CRCW040210K0JNED" 0402 1025,2825 r90 top
R55 "CRCW0402210KFKED" 0402 940,3490 r270 bottom
R56 "CRCW04024K70JNED" 0402 2290,3220 r0 bottom
R57 "CRCW04024K70JNED" 0402 2290,3220 r0 top
R58 "CRCW040210K0JNED" 0402 2290,3160 r0 bottom
R59 "CRCW040210K0JNED" 0402 2710,2550 r90 top
R60 "CRCW040210K0JNED" 0402 2720,2400 r270 top
R61 "CRCW040210K0JNED" 0402 3145,2500 r270 top
R62 "CRCW04020000Z0ED" 0402 2675,2400 r90 top
R63 "CRCW040210K0JNED" 0402 3175,2425 r180 top
R64 "CRCW04022K20JNED" 0402 2290,3160 r0 top
R65 "CRCW040210K0JNED" 0402 1455,2615 r270 top
R66 "CRCW040210K0JNED" 0402 1415,2615 r270 top
R67 "CRCW040210K0JNED" 0402 1455,2615 r270 bottom
R68 "CRCW04022K20JNED" 0402 2100,3105 r180 bottom
R69 "CRCW040233R0JNED" 0402 1725,2615 r90 top
R70 "CRCW040233R0JNED" 0402 1590,2615 r90 top
R71 "CRCW040233R0JNED" 0402 1770,2615 r90 bottom
R72 "CRCW040210K0JNED" 0402 2290,3120 r0 top
R73 "CRCW040233R0JNED" 0402 1725,2615 r90 bottom
R74 "CRCW040210K0JNED" 0402 1200,4285 r90 top
R75 "CRCW040210K0JNED" 0402 1545,2615 r90 bottom
R76 "CRCW040210K0JNED" 0402 1835,3335 r0 top
R77 "CRCW04020000Z0ED" 0402 1550,2895 r270 top
R78 "ERJ-2GE0R00X" 0402 1965,3450 r0 top
R79 "CRCW04021M00JNED" 0402 2035,2865 r270 bottom
R80 "CRCW04020000Z0ED" 0402 2250,3005 r180 bottom
R81 "CRCW04020000Z0ED" 0402 2250,2955 r180 bottom
R82 "CRCW040210K0JNED" 0402 1635,2615 r270 bottom
R83 "CRCW040210K0JNED" 0402 1635,2615 r270 top
R84 "CRCW04024K70JNED" 0402 1680,2615 r90 bottom
R85 "CRCW04024K70JNED" 0402 1680,2615 r90 top
R86 "CRCW04024K70JNED" 0402 1100,4285 r90 bottom
R87 "CRCW04024K70JNED" 0402 1100,4285 r90 top
R88 "CRCW040210K0JNED" 0402 1160,4285 r90 bottom
R89 "CRCW040210K0JNED" 0402 2690,3505 r90 top
R90 "CRCW040210K0JNED" 0402 2710,3355 r270 top
R91 "CRCW040210K0JNED" 0402 3140,3460 r270 top
R92 "CRCW04020000Z0ED" 0402 2665,3355 r90 top
R93 "CRCW040210K0JNED" 0402 3170,3380 r180 top
R94 "CRCW04022K20JNED" 0402 1160,4285 r90 top
R95 "CRCW040210K0JNED" 0402 1705,3500 r0 top
R96 "CRCW040210K0JNED" 0402 1705,3460 r0 top
R97 "CRCW040210K0JNED" 0402 1705,3500 r0 bottom
R98 "CRCW04022K20JNED" 0402 1215,4095 r270 bottom
R99 "CRCW040233R0JNED" 0402 1705,3720 r180 top
R100 "CRCW040233R0JNED" 0402 1705,3585 r180 top
R101 "CRCW040233R0JNED" 0402 1705,3765 r180 bottom
R102 "CRCW040210K0JNED" 0402 5165,1930 r90 top
R103 "CRCW040233R0JNED" 0402 1705,3720 r180 bottom
R104 "CRCW040210K0JNED" 0402 4410,590 r270 top
R105 "CRCW040210K0JNED" 0402 1705,3540 r180 bottom
R106 "CRCW040210K0JNED" 0402 990,3830 r90 top
R107 "CRCW04020000Z0ED" 0402 1425,3540 r0 top
R108 "ERJ-2GE0R00X" 0402 905,4085 r270 top
R109 "CRCW04021M00JNED" 0402 1465,4030 r0 bottom
R110 "CRCW04020000Z0ED" 0402 1320,4190 r270 bottom
R111 "CRCW04020000Z0ED" 0402 1365,4190 r270 bottom
R112 "CRCW040210K0JNED" 0402 1705,3630 r0 bottom
R113 "CRCW040210K0JNED" 0402 1705,3630 r0 top
R114 "CRCW04024K70JNED" 0402 1705,3675 r180 bottom
R115 "CRCW04024K70JNED" 0402 1705,3675 r180 top
R116 "CRCW040210K0JNED" 0402 4675,285 r0 top
R117 "CRCW040249K9FKED" 0402 2065,5635 r90 top
R118 "CRCW0402220RJNED" 0402 4460,215 r270 top
R119 "CRCW040210K0JNED" 0402 4465,590 r270 top
R120 "CRCW040210K0JNED" 0402 4520,590 r270 top
R121 "CRCW04024K70JNED" 0402 3755,1850 r0 top
R122 "CRCW04024K70JNED" 0402 3755,1750 r0 top
R123 "CRCW04024K70JNED" 0402 4025,1880 r0 top
R124 "CRCW04024K70JNED" 0402 4025,1840 r0 top
R125 "CRCW04022K20JNED" 0402 3505,6515 r270 top
R126 "CRCW04020000Z0ED" 0402 4430,1475 r0 top
R127 "CRCW04022K20JNED" 0402 3595,6515 r90 top
R128 "CRCW04020000Z0ED" 0402 4430,1430 r0 top
R129 "CRCW040210K0JNED" 0402 3780,5655 r90 top
R130 "CRCW0402360RJNED" 0402 3885,6515 r90 top
R131 "CRCW0402470RJNED" 0402 3775,6515 r270 top
R132 "CRCW0402220RJNED" 0402 3685,6515 r270 top
R133 "CRCW040210K0JNED" 0402 1770,2615 r90 top
R134 "CRCW040210K0JNED" 0402 1545,2615 r90 top
R135 "CRCW06034K70JNEA" 0603 3955,1980 r270 top
R136 "CRCW08050000Z0EA" 0805_HV 1870,2760 r0 top
R137 "CRCW040210K0JNED" 0402 1705,3765 r180 top
R138 "CRCW040210K0JNED" 0402 1705,3540 r180 top
R139 "CRCW08050000Z0EA" 0805_HV 1565,3860 r90 top
R140 "CRCW04024K99FKED" 0402 3250,6060 r0 top
R141 "CRCW040210K0JNED" 0402 5150,285 r180 top
R142 "CRCW06030000Z0EA" 0603 6520,1310 r270 top
R143 "CRCW0402200RJNED" 0402 4450,2250 r180 top
R144 "CRCW040210K0JNED" 0402 4575,590 r270 top
R145 "CRCW0402200RJNED" 0402 4450,2350 r180 top
R146 "CRCW040210K0JNED" 0402 4575,455 r90 top
R147 "CRCW0402200RJNED" 0402 4450,2450 r180 top
R148 "CRCW040210K0JNED" 0402 4520,455 r90 top
R149 "CRCW040210K0JNED" 0402 4465,455 r90 top
R150 "CRCW040210K0JNED" 0402 4410,455 r90 top
R151 "ERJ-2GE0R00X" 0402 4760,4260 r270 bottom
R152 "ERJ-2GE0R00X" 0402 4725,3680 r270 bottom
R153 "CRCW06034K70JNEA" 0603 3985,1565 r270 top
R154 "CRCW04024K12FKED" 0402 885,2665 r270 top
R155 "CRCW04024K99FKED" 0402 930,2665 r90 top
R156 "CRCW06030000Z0EA" 0603 4575,1675 r180 top
R157 "CRCW04021M00JNED" 0402 4430,1340 r0 top
R158 "CRCW04021M00JNED" 0402 4430,1565 r0 top
R159 "CRCW0402100RFKED" 0402 1500,2615 r270 top
R160 "CRCW04021M00JNED" 0402 5150,1570 r180 top
R161 "CRCW04021M00JNED" 0402 5150,1435 r180 top
R162 "CRCW0402100RFKED" 0402 1565,3595 r90 bottom
R163 "CRCW04020000Z0ED" 0402 4430,1520 r0 top
R164 "CRCW04020000Z0ED" 0402 4430,1385 r0 top
R165 "CRCW04020000Z0ED" 0402 5150,1480 r180 top
R166 "CRCW04020000Z0ED" 0402 5150,1525 r180 top
R167 "CRCW06034K70JNEA" 0603 3955,1290 r90 top
R168 "CRCW0402487RFKED" 0402 4280,215 r270 top
R171 "CRCW06034K70JNEA" 0603 3755,1100 r0 top
R172 "CRCW06034K70JNEA" 0603 3755,1200 r0 top
R173 "CRCW0402487RFKED" 0402 4370,215 r270 top
R174 "ERJ-2GE0R00X" 0402 5135,4260 r270 bottom
R175 "ERJ-2GE0R00X" 0402 5135,3785 r270 bottom
R176 "ERJ-2GE0R00X" 0402 4980,4365 r270 bottom
R177 "ERJ-2GE0R00X" 0402 4980,3785 r270 bottom
R178 "ERJ-2GE0R00X" 0402 4950,4260 r270 bottom
R179 "ERJ-2GE0R00X" 0402 4945,3680 r270 bottom
R180 "ERJ-2GE0R00X" 0402 4915,4365 r270 bottom
R181 "ERJ-2GE0R00X" 0402 4915,3785 r270 bottom
R182 "ERJ-2GE0R00X" 0402 4885,4260 r270 bottom
R184 "CRCW040210K0JNED" 0402 3250,6105 r180 top
R185 "CRCW040210K0JNED" 0402 4975,1315 r0 top
R186 "ERJ-2GE0R00X" 0402 4695,3785 r270 bottom
R187 "ERJ-2GE0R00X" 0402 4665,4260 r270 bottom
R188 "ERJ-2GE0R00X" 0402 4600,4260 r270 bottom
R189 "ERJ-2GE0R00X" 0402 4535,4260 r90 bottom
R190 "ERJ-2GE0R00X" 0402 4535,3785 r270 bottom
R191 "ERJ-2GE0R00X" 0402 4350,4365 r270 bottom
R192 "ERJ-2GE0R00X" 0402 4350,3680 r270 bottom
R193 "ERJ-2GE0R00X" 0402 4315,4260 r270 bottom
R194 "ERJ-2GE0R00X" 0402 4315,3785 r270 bottom
R195 "ERJ-2GE0R00X" 0402 4285,4365 r270 bottom
R196 "ERJ-2GE0R00X" 0402 4285,3680 r270 bottom
R197 "ERJ-2GE0R00X" 0402 4250,4260 r270 bottom
R198 "ERJ-2GE0R00X" 0402 4250,3785 r270 bottom
R199 "ERJ-2GE0R00X" 0402 4035,4365 r270 bottom
R200 "ERJ-2GE0R00X" 0402 4040,3680 r270 bottom
R201 "CRCW040210K0JNED" 0402 3780,5155 r90 top
R202 "ERJ-2GE0R00X" 0402 4005,4260 r270 bottom
R203 "ERJ-2GE0R00X" 0402 4005,3785 r270 bottom
R204 "CRCW040210K0JNED" 0402 3780,4665 r90 top
R205 "ERJ-2GE0R00X" 0402 3940,4260 r270 bottom
R206 "ERJ-2GE0R00X" 0402 3940,3785 r270 bottom
R207 "ERJ-2GE0R00X" 0402 3910,4365 r270 bottom
R208 "ERJ-2GE0R00X" 0402 3910,3680 r270 bottom
R209 "ERJ-2GE0R00X" 0402 3875,4260 r270 bottom
R210 "ERJ-2GE0R00X" 0402 3875,3785 r270 bottom
R211 "ERJ-2GE0R00X" 0402 3845,4365 r270 bottom
R212 "ERJ-2GE0R00X" 0402 3845,3680 r270 bottom
R213 "ERJ-2GE0R00X" 0402 3810,4260 r270 bottom
R214 "ERJ-2GE0R00X" 0402 3810,3785 r270 bottom
R215 "ERJ-2GE0R00X" 0402 3745,4260 r270 bottom
R216 "ERJ-2GE0R00X" 0402 3745,3785 r270 bottom
R217 "ERJ-2GE0R00X" 0402 3595,4260 r270 bottom
R218 "ERJ-2GE0R00X" 0402 3560,3680 r270 bottom
R219 "ERJ-2GE0R00X" 0402 3530,4260 r270 bottom
R220 "ERJ-2GE0R00X" 0402 3530,3785 r270 bottom
R221 "ERJ-2GE0R00X" 0402 3495,4365 r270 bottom
R222 "ERJ-2GE0R00X" 0402 3465,3785 r270 bottom
R223 "ERJ-2GE0R00X" 0402 3465,4260 r270 bottom
R224 "ERJ-2GE0R00X" 0402 3185,3785 r270 bottom
S1 "SKRKAEE010" SW_SKRKAEE010 4675,155 r0 top
S2 "SKRKAEE010" SW_SKRKAEE010 5175,155 r180 top
TP1 "5000" Keystone5000 5100,6300 r90 top
TP2 "5000" Keystone5000 4900,6300 r90 top
TP3 "5000" Keystone5000 4700,6300 r90 top
TP4 "5000" Keystone5000 4500,6300 r90 top
TP5 "5000" Keystone5000 1450,5850 r90 top
TP6 "5000" Keystone5000 2500,5850 r90 top
TP7 "5000" Keystone5000 3710,6290 r0 top
TP8 "5001" Keystone5001 5300,6300 r90 top
TP9 "5000" Keystone5000 3290,5250 r0 top
TP10 "5000" Keystone5000 4300,5750 r90 top
TP11 "5001" Keystone5001 1040,2035 r90 top
TP12 "5000" Keystone5000 4300,5250 r90 top
TP13 "5001" Keystone5001 900,5595 r90 top
TP14 "5000" Keystone5000 4300,4750 r90 top
TP15 "5001" Keystone5001 4180,2350 r90 top
TP16 "TP-025-SMT" TP_25MIL-SMT 715,3135 r90 top
TP17 "TP-025-SMT" TP_25MIL-SMT 715,3100 r90 top
TP18 "5015" Testpoint_Keystone_Miniature 3135,2180 r270 top
TP19 "5015" Testpoint_Keystone_Miniature 2980,2180 r270 top
TP20 "5015" Testpoint_Keystone_Miniature 2820,2180 r270 top
TP21 "5015" Testpoint_Keystone_Miniature 3110,3125 r90 top
TP22 "5015" Testpoint_Keystone_Miniature 2960,3125 r270 top
TP23 "5015" Testpoint_Keystone_Miniature 2810,3125 r270 top
TP24 "5004" Keystone5004 4180,2150 r90 top
TP25 "5004" Keystone5004 4180,1950 r90 top
TP26 "5004" Keystone5004 4180,1750 r90 top
TP27 "5004" Keystone5004 4180,1550 r180 top
TP28 "5004" Keystone5004 4180,1300 r90 top
TP29 "Pogo Pad" PogoPad 1310.5,4225 r270 top
TP30 "Pogo Pad" PogoPad 1410.5,4225 r270 top
TP31 "Pogo Pad" PogoPad 1510.5,4225 r90 top
TP32 "Pogo Pad" PogoPad 1510.5,4125 r270 top
TP33 "Pogo Pad" PogoPad 2275,3025 r270 top
TP34 "Pogo Pad" PogoPad 2275,2925 r270 top
TP35 "Pogo Pad" PogoPad 2275,2825 r270 top
TP36 "Pogo Pad" PogoPad 2175,2825 r270 top
TP37 "Pogo Pad" PogoPad 2585,3025 r180 top
TP38 "Pogo Pad" PogoPad 2585,2925 r180 top
TP39 "Pogo Pad" PogoPad 2485,2825 r180 top
TP40 "Pogo Pad" PogoPad 2585,2825 r180 top
TP41 "Pogo Pad" PogoPad 1545,2720 r0 top
TP42 "Pogo Pad" PogoPad 1595,3540 r180 top
TP43 "5001" Keystone5001 3200,1300 r0 top
TP44 "5001" Keystone5001 6000,3855 r0 top
TP45 "5001" Keystone5001 5750,150 r0 top
TP46 "5001" Keystone5001 960,4350 r0 top
TP47 "Pogo Pad" PogoPad 1300,4535 r90 top
TP48 "Pogo Pad" PogoPad 1400,4535 r90 top
TP49 "Pogo Pad" PogoPad 1500,4435 r90 top
TP50 "Pogo Pad" PogoPad 1500,4535 r90 top
U1 "DS90UB960QRTD" RTD0064E 1125,3117.5 r90 top locked
U2 "TLVH431AQDBVRQ1A" DBV0005A_N 360,5760 r180 top
U3 "SN74LVC1G125DCKR" DCK0005A_N 5050,5570 r0 top
U4 "TPS1H100BQPWPRQ1" PWP0014C_N 3465,6135 r180 top
U5 "TPS62160QDSGRQ1" DSG0008A 3865,5720 r0 top
U6 "TPS62160QDSGRQ1" DSG0008A 3865,5220 r0 top
U7 "TPS62160QDSGRQ1" DSG0008A 3865,4730 r0 top
U8 "OV00490-B00G-1A-Z" OVT_OV490 1900,3075 r90 bottom locked
U10 "W25Q128FVSIG" SOIC127P800X216-8N 2930,2450 r0 top locked
U12 "OV00490-B00G-1A-Z" OVT_OV490 1246.24,3892.5 r180 bottom
U14 "W25Q128FVSIG" SOIC127P800X216-8N 2915,3405 r0 top
U16 "MSP430F2272TDAQ1" DA0038A_N 4850,1600 r0 top locked
U17 "TS3USB221AQRSERQ1" RSE0010A 3905,1860 r0 top
U18 "TS3USB221AQRSERQ1" RSE0010A 3905,1485 r0 top
U19 "TS3USB221AQRSERQ1" RSE0010A 3905,1170 r0 top
U20 "TPS55340QRTERQ1" RTE0016C 1840,5715 r0 top
U21 "SN74LVC1G125DCKR" DCK0005A_N 5050,5400 r0 top
U23 "SN74LVC1G125DCKR" DCK0005A_N 5050,5230 r0 top
Y1 "7C-25.000MCB-T" TXC_7C 1031.2,2535 r180 top
Y2 "ABM10-24.576MHZ-E20-T" XTAL_ABM10 2130,2855 r180 bottom
Y3 "ABM10-24.576MHZ-E20-T" XTAL_ABM10 1470,4130 r270 bottom
ZZ1 "These assemblies are ESD sensitive, ESD precautions shall be observed." AssemblyNote 200,7000 r0 top
ZZ2 "These assemblies must be clean and free from flux and all contaminants. Use of no clean flux is not acceptable." AssemblyNote 200,6900 r0 top
ZZ3 "These assemblies must comply with workmanship standards IPC-A-610 Class 2, unless otherwise specified." AssemblyNote 200,6800 r0 top

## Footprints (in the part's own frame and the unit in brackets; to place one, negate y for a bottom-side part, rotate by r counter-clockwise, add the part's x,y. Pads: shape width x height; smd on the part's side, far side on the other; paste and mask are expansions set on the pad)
0402 [mm] "0402 from SM-752 data"
  rect 0.8x0.6 smd: 1(-0.6,0) 2(0.6,0)
  silkscreen extent -1.22,-0.52 1.22,0.52, body extent -0.55,-0.3 0.55,0.3, height 0.6
0603 [mm] "0603 from SM-752 data"
  rect 1x0.95 smd: 1(-0.8,0) 2(0.8,0)
  silkscreen extent -1.52,-0.69 1.52,0.69, body extent -0.87,-0.47 0.87,0.47, height 0.85
0603L [mm] "0603 from SM-752 data"
  rect 0.8x0.85 smd: 1(-0.7,0) 2(0.7,0)
  silkscreen extent -0.07,-0.33 0.07,0.33, body extent -0.87,-0.47 0.87,0.47, height 0.85
0805 [mm] "0805 from SM-752 data"
  rect 1.3x1.5 smd: 1(-0.85,0) 2(0.85,0)
  silkscreen extent -1.72,-0.97 1.72,0.97, body extent -1.1,-0.72 1.1,0.72, height 1.1
0805_HV [mil] "0805 with 30mil clearance between pads"
  rect 50x63 smd: 1(-40,0) 2(40,0)
  silkscreen extent -74,-40 74,40, body extent -43,-29 43,29, height 43
1206 [mm] "1206 from SM-752 data"
  rect 1.3x1.85 smd: 1(-1.45,0) 2(1.45,0)
  silkscreen extent -2.4,-1.21 2.4,1.21, body extent -1.7,-0.9 1.7,0.9, height 1.35
1210 [mm] "1210 from SM-752 data"
  rect 1.3x2.7 smd: 1(-1.45,0) 2(1.45,0)
  silkscreen extent -2.32,-1.57 2.32,1.57, body extent -1.7,-1.35 1.7,1.35, height 1.35
2010 [mm] "Chip Capacitor, Body 5.08x2.54mm, IPC Medium Density"
  rect 1.6x2.7 smd: 1(-2.3,0) 2(2.3,0)
  silkscreen extent -3.42,-1.65 3.42,1.65, body extent -2.73,-1.45 2.73,1.45, height 1.66
AssemblyNote [mil] "Assembly Note"
CONN_851-43-006-20-001000 [mil] "Mill-Max"
  rect 36x70 hole 26: 1(125,0)
  oval 36x70 hole 26: 2(75,0) 3(25,0) 4(-25,0) 5(-75,0) 6(-125,0)
  silkscreen extent -160,-210 160,-72, body extent -157,-210 157,8, height 87
CONN_PEC02SAAN [mm] "SULLINS"
  rect 1.5x1.5 hole 1.016: 1(-1.27,0)
  round 1.5 hole 1.016: 2(1.27,0)
  silkscreen extent -3.45,-1.27 2.54,1.27, body extent -2.54,-1.27 2.54,1.27, height 8.38
DA0038A_N [mm] "TSOP, 38-Leads, Body 12.6x6.2mm (max), Pitch 0.65mm, IPC Medium Density"
  oval 1.7x0.35 smd: 1(-3.7,5.85) 2(-3.7,5.2) 3(-3.7,4.55) 4(-3.7,3.9) 5(-3.7,3.25) 6(-3.7,2.6) 7(-3.7,1.95) 8(-3.7,1.3) 9(-3.7,0.65) 10(-3.7,0) 11(-3.7,-0.65) 12(-3.7,-1.3) 13(-3.7,-1.95) 14(-3.7,-2.6) 15(-3.7,-3.25) 16(-3.7,-3.9) 17(-3.7,-4.55) 18(-3.7,-5.2) 19(-3.7,-5.85) 20(3.7,-5.85) 21(3.7,-5.2) 22(3.7,-4.55) 23(3.7,-3.9) 24(3.7,-3.25) 25(3.7,-2.6) 26(3.7,-1.95) 27(3.7,-1.3) 28(3.7,-0.65) 29(3.7,0) 30(3.7,0.65) 31(3.7,1.3) 32(3.7,1.95) 33(3.7,2.6) 34(3.7,3.25) 35(3.7,3.9) 36(3.7,4.55) 37(3.7,5.2) 38(3.7,5.85)
  silkscreen extent -2.45,-6.3 2.45,6.3, body extent -4.17,-6.3 4.11,6.3, height 1.2
DBV0005A_N [mm] "SOT23, 5-Leads, Body 2.9x1.6mm, Pitch 0.95mm, Lead Span 2.8mm, IPC Medium Density"
  rect 1.1x0.65 smd: 1(-1.2,0.95) 2(-1.2,0) 3(-1.2,-0.95) 4(1.2,-0.95) 5(1.2,0.95)
  silkscreen extent -0.25,-1.55 0.25,1.55, body extent -1.42,-1.46 1.42,1.46, height 1.08
DCK0005A_N [mm] "SOT353, 5-Leads, Body 2x1.3mm, Pitch 0.65mm, Lead Span 2.1mm, IPC Medium Density"
  rect 0.85x0.4 smd: 1(-0.95,0.65) 2(-0.95,0) 3(-0.95,-0.65) 4(0.95,-0.65) 5(0.95,0.65)
  silkscreen extent -0.15,-1.1 0.15,1.1, body extent -1.14,-1 1.14,1, height 0.94
DRQ127 [mm] "COILTRONICS"
  rect 3.85x2.5 smd: 1(-4.975,1.5) 2(-4.975,-1.5) 3(4.975,-1.5) 4(4.975,1.5)
  silkscreen extent -6.7,-6.3 6.3,6.3, body extent -6.26,-6.26 6.26,6.26, height 8.01
DSG0008A [mm] "SON, 8-Leads, Body 2x2mm, Pitch 0.5mm, Thermal Pad 1.6x0.9mm, TI Recommended"
  rect 0.5x0.25 smd: 1(-0.95,0.75) 2(-0.95,0.25) 3(-0.95,-0.25) 4(-0.95,-0.75) 5(0.95,-0.75) 6(0.95,-0.25) 7(0.95,0.25) 8(0.95,0.75)
  rect 0.9x1.6 smd paste-0.45: 9(0,0)
  silkscreen extent -1.07,-1.15 1.07,1.15, body extent -1.05,-1.05 1.05,1.05, height 0.8
Fiducial10-20 [mm]
  round 1 smd mask+0.5: 1(0,0)
Keystone5000 [mil] "For Keystone 500x miniature loop terminals"
  round 80 hole 40: 1(0,0)
  silkscreen extent -58,-58 58,58, body extent -49,-49 49,49, height 182
Keystone5001 [mil] "For Keystone 500x miniature loop terminals"
  round 80 hole 40: 1(0,0)
  silkscreen extent -58,-58 58,58, body extent -49,-49 49,49, height 182
Keystone5004 [mil] "For Keystone 500x miniature loop terminals"
  round 80 hole 40: 1(0,0)
  silkscreen extent -58,-58 58,58, body extent -49,-49 49,49, height 182
LED_SMLP12_ORANGE [mm] "Rohm Semiconductor"
  rect 0.5x0.6 smd mask+0.08: 1(-0.45,0) 2(0.45,0)
  silkscreen extent 0.92,-0.3 0.92,0.3, body extent -0.55,-0.35 0.55,0.35, height 0.25
LED_SMLP12_Yellow [mm] "Rohm Semiconductor"
  rect 0.5x0.6 smd mask+0.08: 1(-0.45,0) 2(0.45,0)
  silkscreen extent 0.92,-0.3 0.92,0.3, body extent -0.55,-0.35 0.55,0.35, height 0.25
LQH3NP_G0 [mm] "MURATA"
  rect 1.15x3.3 smd: 1(-1.075,0) 2(1.075,0)
  body extent -1.6,-1.6 1.6,1.6, height 1.01
MSS7341 [mm] "Coilcraft recommended land pattern Document 383-2 1/3/11"
  rect 0.7x7.1 smd: 1(-3.2,0) 2(3.2,0)
  Layer 1 - Top Layer region: -1.05,3.55 -3.55,3.55 -3.55,-3.55 -1.05,-3.55 -1.05,-2.623 -2.135,-1.85 -2.745,-0.666 -2.745,0.666 -2.135,1.85 -1.05,2.623 -1.05,2.623
  Layer 1 - Top Layer region: 1.05,3.55 3.55,3.55 3.55,-3.55 1.05,-3.55 1.05,-2.623 2.135,-1.85 2.745,-0.666 2.745,0.666 2.135,1.85 1.05,2.623 1.05,2.623
  silkscreen extent -3.8,-3.8 3.8,3.8, body extent -3.78,-3.78 3.78,3.78, height 4.12
OVT_OV490 [mm] "BGA, 100-Leads, Body 7.00x7.00mmx1.10mm, Pitch 0.65mm"
  round 0.25 smd: A1(-2.925,2.925) A2(-2.275,2.925) A3(-1.625,2.925) A4(-0.975,2.925) A5(-0.325,2.925) A6(0.325,2.925) A7(0.975,2.925) A8(1.625,2.925) A9(2.275,2.925) A10(2.925,2.925) B1(-2.925,2.275) B2(-2.275,2.275) B3(-1.625,2.275) B4(-0.975,2.275) B5(-0.325,2.275) B6(0.325,2.275) B7(0.975,2.275) B8(1.625,2.275) B9(2.275,2.275) B10(2.925,2.275) C1(-2.925,1.625) C2(-2.275,1.625) C3(-1.625,1.625) C4(-0.975,1.625) C5(-0.325,1.625) C6(0.325,1.625) C7(0.975,1.625) C8(1.625,1.625) C9(2.275,1.625) C10(2.925,1.625) D1(-2.925,0.975) D2(-2.275,0.975) D3(-1.625,0.975) D4(-0.975,0.975) D5(-0.325,0.975) D6(0.325,0.975) D7(0.975,0.975) D8(1.625,0.975) D9(2.275,0.975) D10(2.925,0.975) E1(-2.925,0.325) E2(-2.275,0.325) E3(-1.625,0.325) E4(-0.975,0.325) E5(-0.325,0.325) E6(0.325,0.325) E7(0.975,0.325) E8(1.625,0.325) E9(2.275,0.325) E10(2.925,0.325) F1(-2.925,-0.325) F2(-2.275,-0.325) F3(-1.625,-0.325) F4(-0.975,-0.325) F5(-0.325,-0.325) F6(0.325,-0.325) F7(0.975,-0.325) F8(1.625,-0.325) F9(2.275,-0.325) F10(2.925,-0.325) G1(-2.925,-0.975) G2(-2.275,-0.975) G3(-1.625,-0.975) G4(-0.975,-0.975) G5(-0.325,-0.975) G6(0.325,-0.975) G7(0.975,-0.975) G8(1.625,-0.975) G9(2.275,-0.975) G10(2.925,-0.975) H1(-2.925,-1.625) H2(-2.275,-1.625) H3(-1.625,-1.625) H4(-0.975,-1.625) H5(-0.325,-1.625) H6(0.325,-1.625) H7(0.975,-1.625) H8(1.625,-1.625) H9(2.275,-1.625) H10(2.925,-1.625) J1(-2.925,-2.275) J2(-2.275,-2.275) J3(-1.625,-2.275) J4(-0.975,-2.275) J5(-0.325,-2.275) J6(0.325,-2.275) J7(0.975,-2.275) J8(1.625,-2.275) J9(2.275,-2.275) J10(2.925,-2.275) K1(-2.925,-2.925) K2(-2.275,-2.925) K3(-1.625,-2.925) K4(-0.975,-2.925) K5(-0.325,-2.925) K6(0.325,-2.925) K7(0.975,-2.925) K8(1.625,-2.925) K9(2.275,-2.925) K10(2.925,-2.925)
  silkscreen extent -3.5,-3.5 3.5,3.5, body extent -3.5,-3.5 3.5,3.5, height 1.11
Pb-Free_Overlay_Small [mil]
  silkscreen extent -46,-46 46,46
PhoenixConact_1727010 [mm]
  rect 1.7x1.7 hole 1.1: 1(-1.905,0)
  round 1.7 hole 1.1: 2(1.905,0)
  silkscreen extent -4.76,-3.6 3.81,3.6, body extent -3.81,-3.6 3.81,3.7, height 8.52
PogoPad [mil] "No Solder Paste"
  round 70 smd paste-35: 1(0,0)
PowerPAK_SO-8L [mm] "based on Vishay recommended land pattern Document 63818 Feb 7, 2012"
  rect 1x0.41 smd: 1(-2.805,1.905) 2(-2.805,0.635) 3(-2.805,-0.635) 4(-2.805,-1.905)
  rect 3.63x4.061 smd: 5(0.805,0)
  Layer 1 - Top Layer region: 2.615,-2.5 3.125,-2.5 3.125,2.5 2.615,2.5
  Layer 1 - Top Layer region: -0.298,2.03 0.298,2.03 0.298,2.64 -0.298,2.64
  Layer 1 - Top Layer region: -0.298,-2.64 0.298,-2.64 0.298,-2.03 -0.298,-2.03
  body extent -3.07,-2.57 3.08,2.57, height 1.21
PWP0014C_N [mm] "TSOP, 14-Leads, Body 5x4.4mm, Pitch 0.65mm, Thermal Pad 3x3 mm, IPC Medium Density"
  oval 1.7x0.35 smd: 1(-2.85,1.95) 2(-2.85,1.3) 3(-2.85,0.65) 4(-2.85,0) 5(-2.85,-0.65) 6(-2.85,-1.3) 7(-2.85,-1.95) 8(2.85,-1.95) 9(2.85,-1.3) 10(2.85,-0.65) 11(2.85,0) 12(2.85,0.65) 13(2.85,1.3) 14(2.85,1.95)
  rect 2.72x2.5 smd: 15(0,0)
  silkscreen extent -3.47,-2.65 1.7,2.65, body extent -3.21,-2.5 3.21,2.5, height 0.99
Rosenberger_59S20X-400L5 [mm] "Rosenberger"
  rect 2x2 hole 1.5 paste+0: 1(-4.55,0)
  round 2.4 hole 1.9 paste+0: MH1(-7.09,2.54) MH2(-2.01,2.54) MH3(-2.01,-2.54) MH4(-7.09,-2.54)
  silkscreen extent -8.3,-4.25 0,4.25, body extent -8.3,-4.25 8.3,4.25, height 11.61
RSE0010A [mm] "QFN, 10-Leads, Body 1.5x2mm, Pitch 0.5mm, TI Recommended"
  rect 0.55x0.2 smd: 1(-0.675,0.75) 2(-0.675,0.25) 3(-0.675,-0.25) 4(-0.675,-0.75) 6(0.675,-0.75) 7(0.675,-0.25) 8(0.675,0.25) 9(0.675,0.75)
  rect 0.3x0.6 smd: 5(0,-0.9) 10(0,0.9)
  silkscreen extent -1.07,-1.17 0.77,1.18, body extent -0.77,-1.02 0.78,1.03, height 0.61
RTD0064E [mm] "QFN, 64-Leads, Body 9x9mm, Pitch 0.5mm, Thermal Pad 6.1x6.1mm"
  oval 0.6x0.24 smd: 1(-4.4,3.75) 2(-4.4,3.25) 3(-4.4,2.75) 4(-4.4,2.25) 5(-4.4,1.75) 6(-4.4,1.25) 7(-4.4,0.75) 8(-4.4,0.25) 9(-4.4,-0.25) 10(-4.4,-0.75) 11(-4.4,-1.25) 12(-4.4,-1.75) 13(-4.4,-2.25) 14(-4.4,-2.75) 15(-4.4,-3.25) 16(-4.4,-3.75) 33(4.4,-3.75) 34(4.4,-3.25) 35(4.4,-2.75) 36(4.4,-2.25) 37(4.4,-1.75) 38(4.4,-1.25) 39(4.4,-0.75) 40(4.4,-0.25) 41(4.4,0.25) 42(4.4,0.75) 43(4.4,1.25) 44(4.4,1.75) 45(4.4,2.25) 46(4.4,2.75) 47(4.4,3.25) 48(4.4,3.75)
  oval 0.24x0.6 smd: 17(-3.75,-4.4) 18(-3.25,-4.4) 19(-2.75,-4.4) 20(-2.25,-4.4) 21(-1.75,-4.4) 22(-1.25,-4.4) 23(-0.75,-4.4) 24(-0.25,-4.4) 25(0.25,-4.4) 26(0.75,-4.4) 27(1.25,-4.4) 28(1.75,-4.4) 29(2.25,-4.4) 30(2.75,-4.4) 31(3.25,-4.4) 32(3.75,-4.4) 49(3.75,4.4) 50(3.25,4.4) 51(2.75,4.4) 52(2.25,4.4) 53(1.75,4.4) 54(1.25,4.4) 55(0.75,4.4) 56(0.25,4.4) 57(-0.25,4.4) 58(-0.75,4.4) 59(-1.25,4.4) 60(-1.75,4.4) 61(-2.25,4.4) 62(-2.75,4.4) 63(-3.25,4.4) 64(-3.75,4.4)
  rect 6.1x6.1 smd paste-3.5: 65(0,0)
  silkscreen extent -4.7,-4.7 4.7,4.7, body extent -4.55,-4.55 4.55,4.55, height 0.91
RTE0016C [mm] "Texas Insturments"
  oval 0.6x0.24 smd: 1(-1.4,0.75) 2(-1.4,0.25) 3(-1.4,-0.25) 4(-1.4,-0.75) 9(1.4,-0.75) 10(1.4,-0.25) 11(1.4,0.25) 12(1.4,0.75)
  oval 0.24x0.6 smd: 5(-0.75,-1.4) 6(-0.25,-1.4) 7(0.25,-1.4) 8(0.75,-1.4) 13(0.75,1.4) 14(0.25,1.4) 15(-0.25,1.4) 16(-0.75,1.4)
  rect 1.7x1.7 smd paste-0.85: 17(0,0)
  silkscreen extent -1.73,-1.73 1.73,1.73, body extent -1.57,-1.57 1.58,1.58, height 0.81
